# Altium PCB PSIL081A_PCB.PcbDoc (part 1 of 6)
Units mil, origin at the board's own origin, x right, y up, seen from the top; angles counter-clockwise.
Board outline 14000 x 8000 mil, 10 copper layers (Top Layer, Signal Layer 1, Signal Layer 2, Signal Layer 3, Signal Layer 4, Signal Layer 5, Signal Layer 6, Signal Layer 7, Signal Layer 8, Bottom Layer), stack 60.9 mil thick; 433 components, 510 nets, 1716 pads, 590 vias.
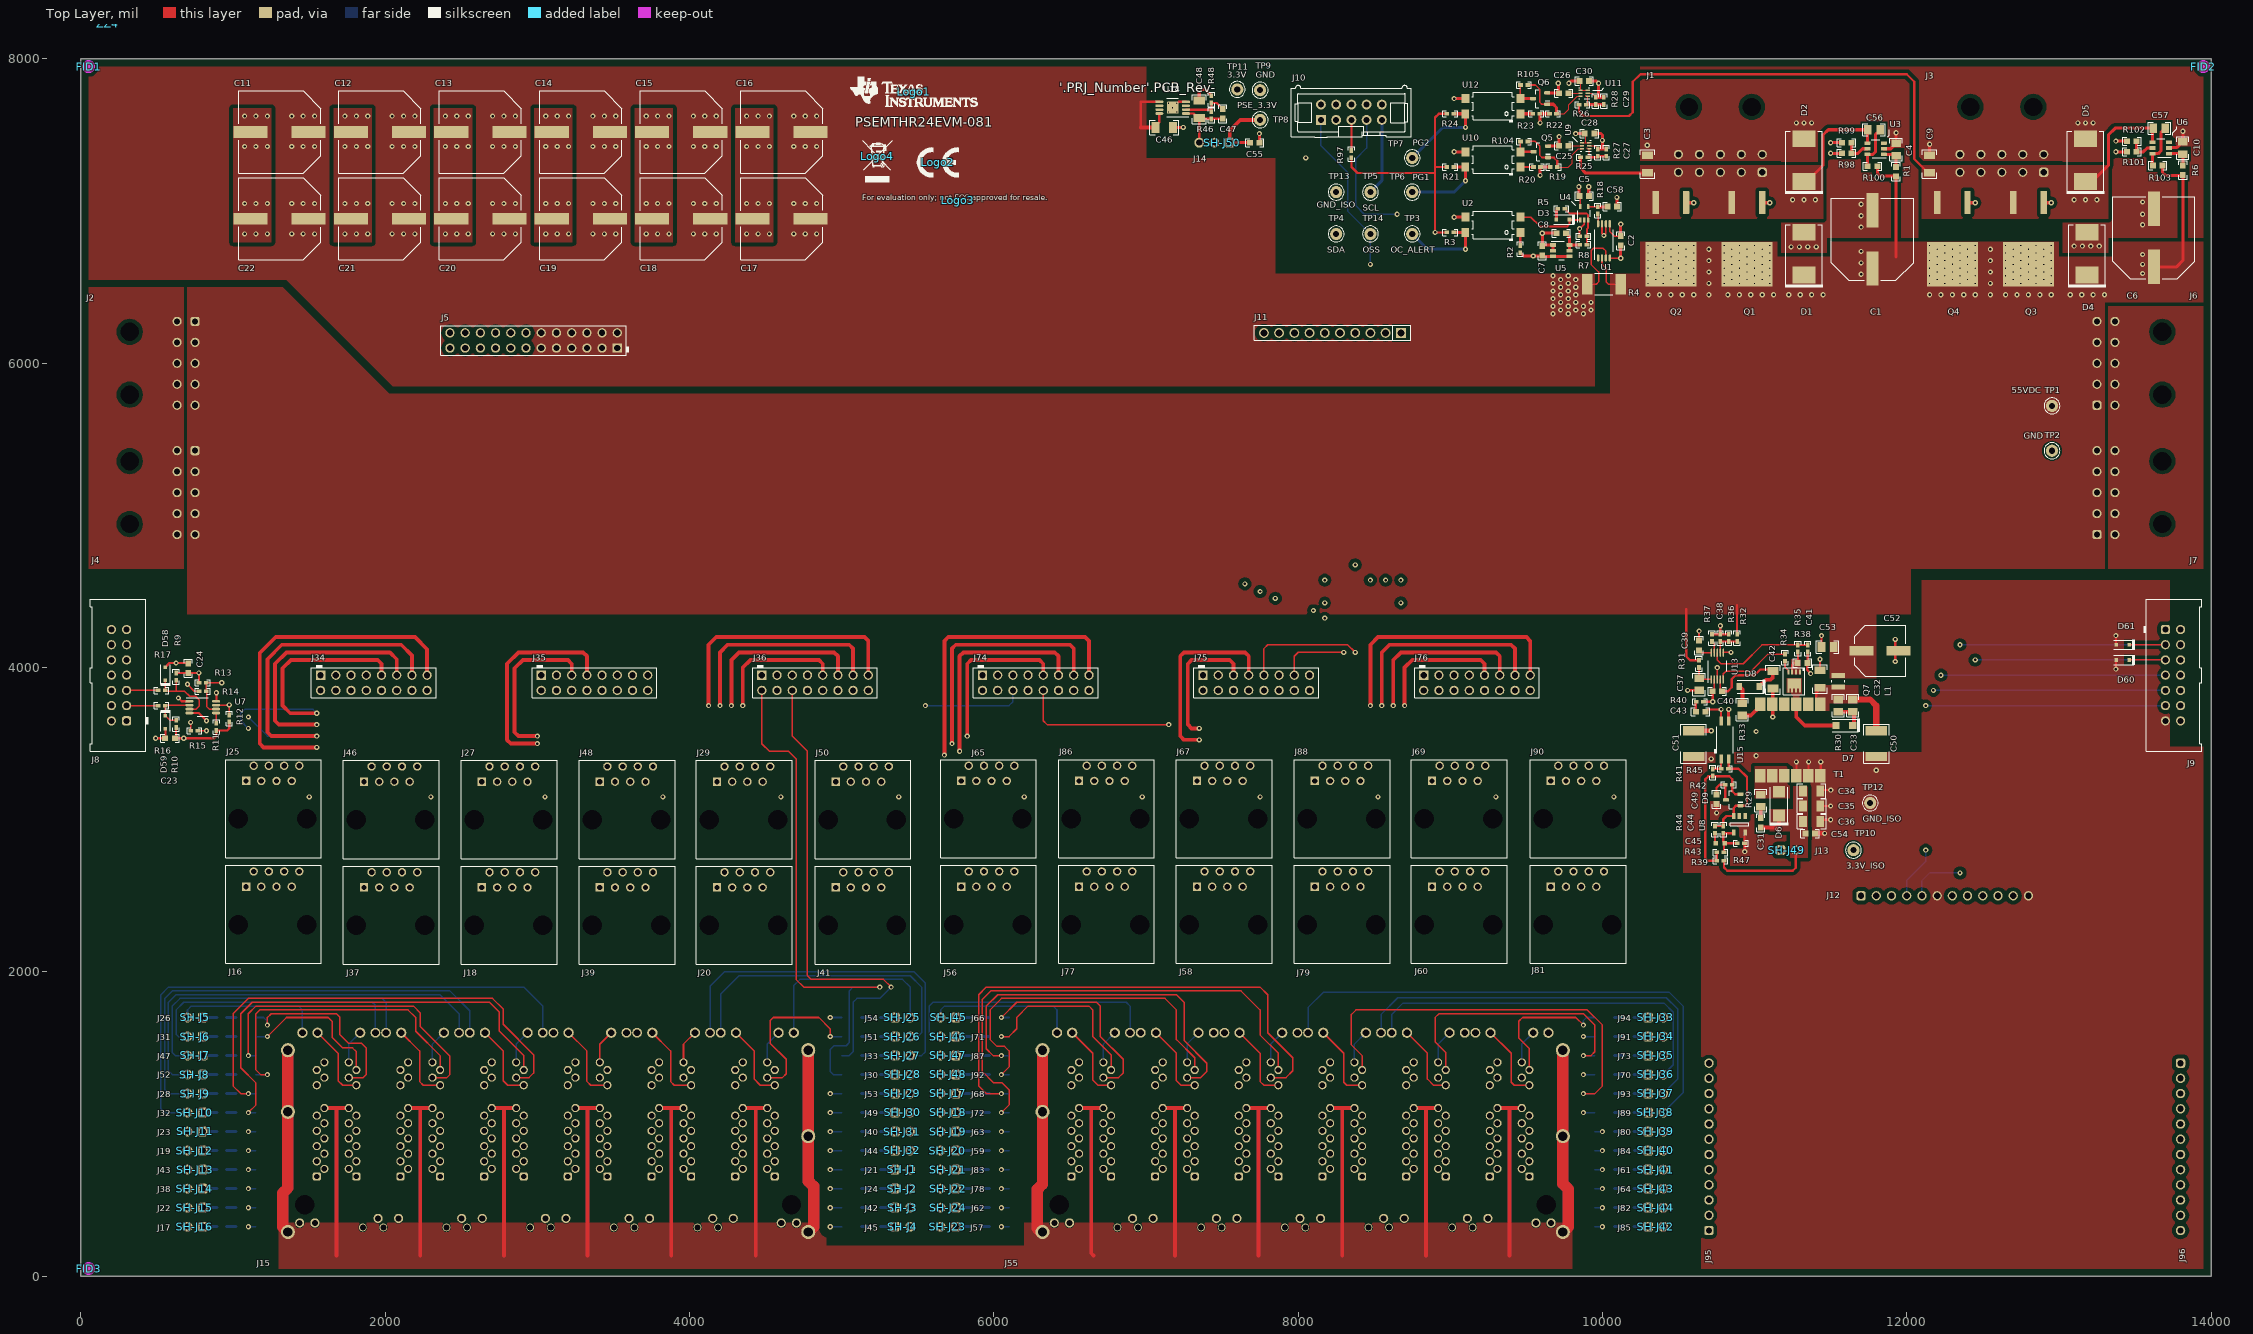
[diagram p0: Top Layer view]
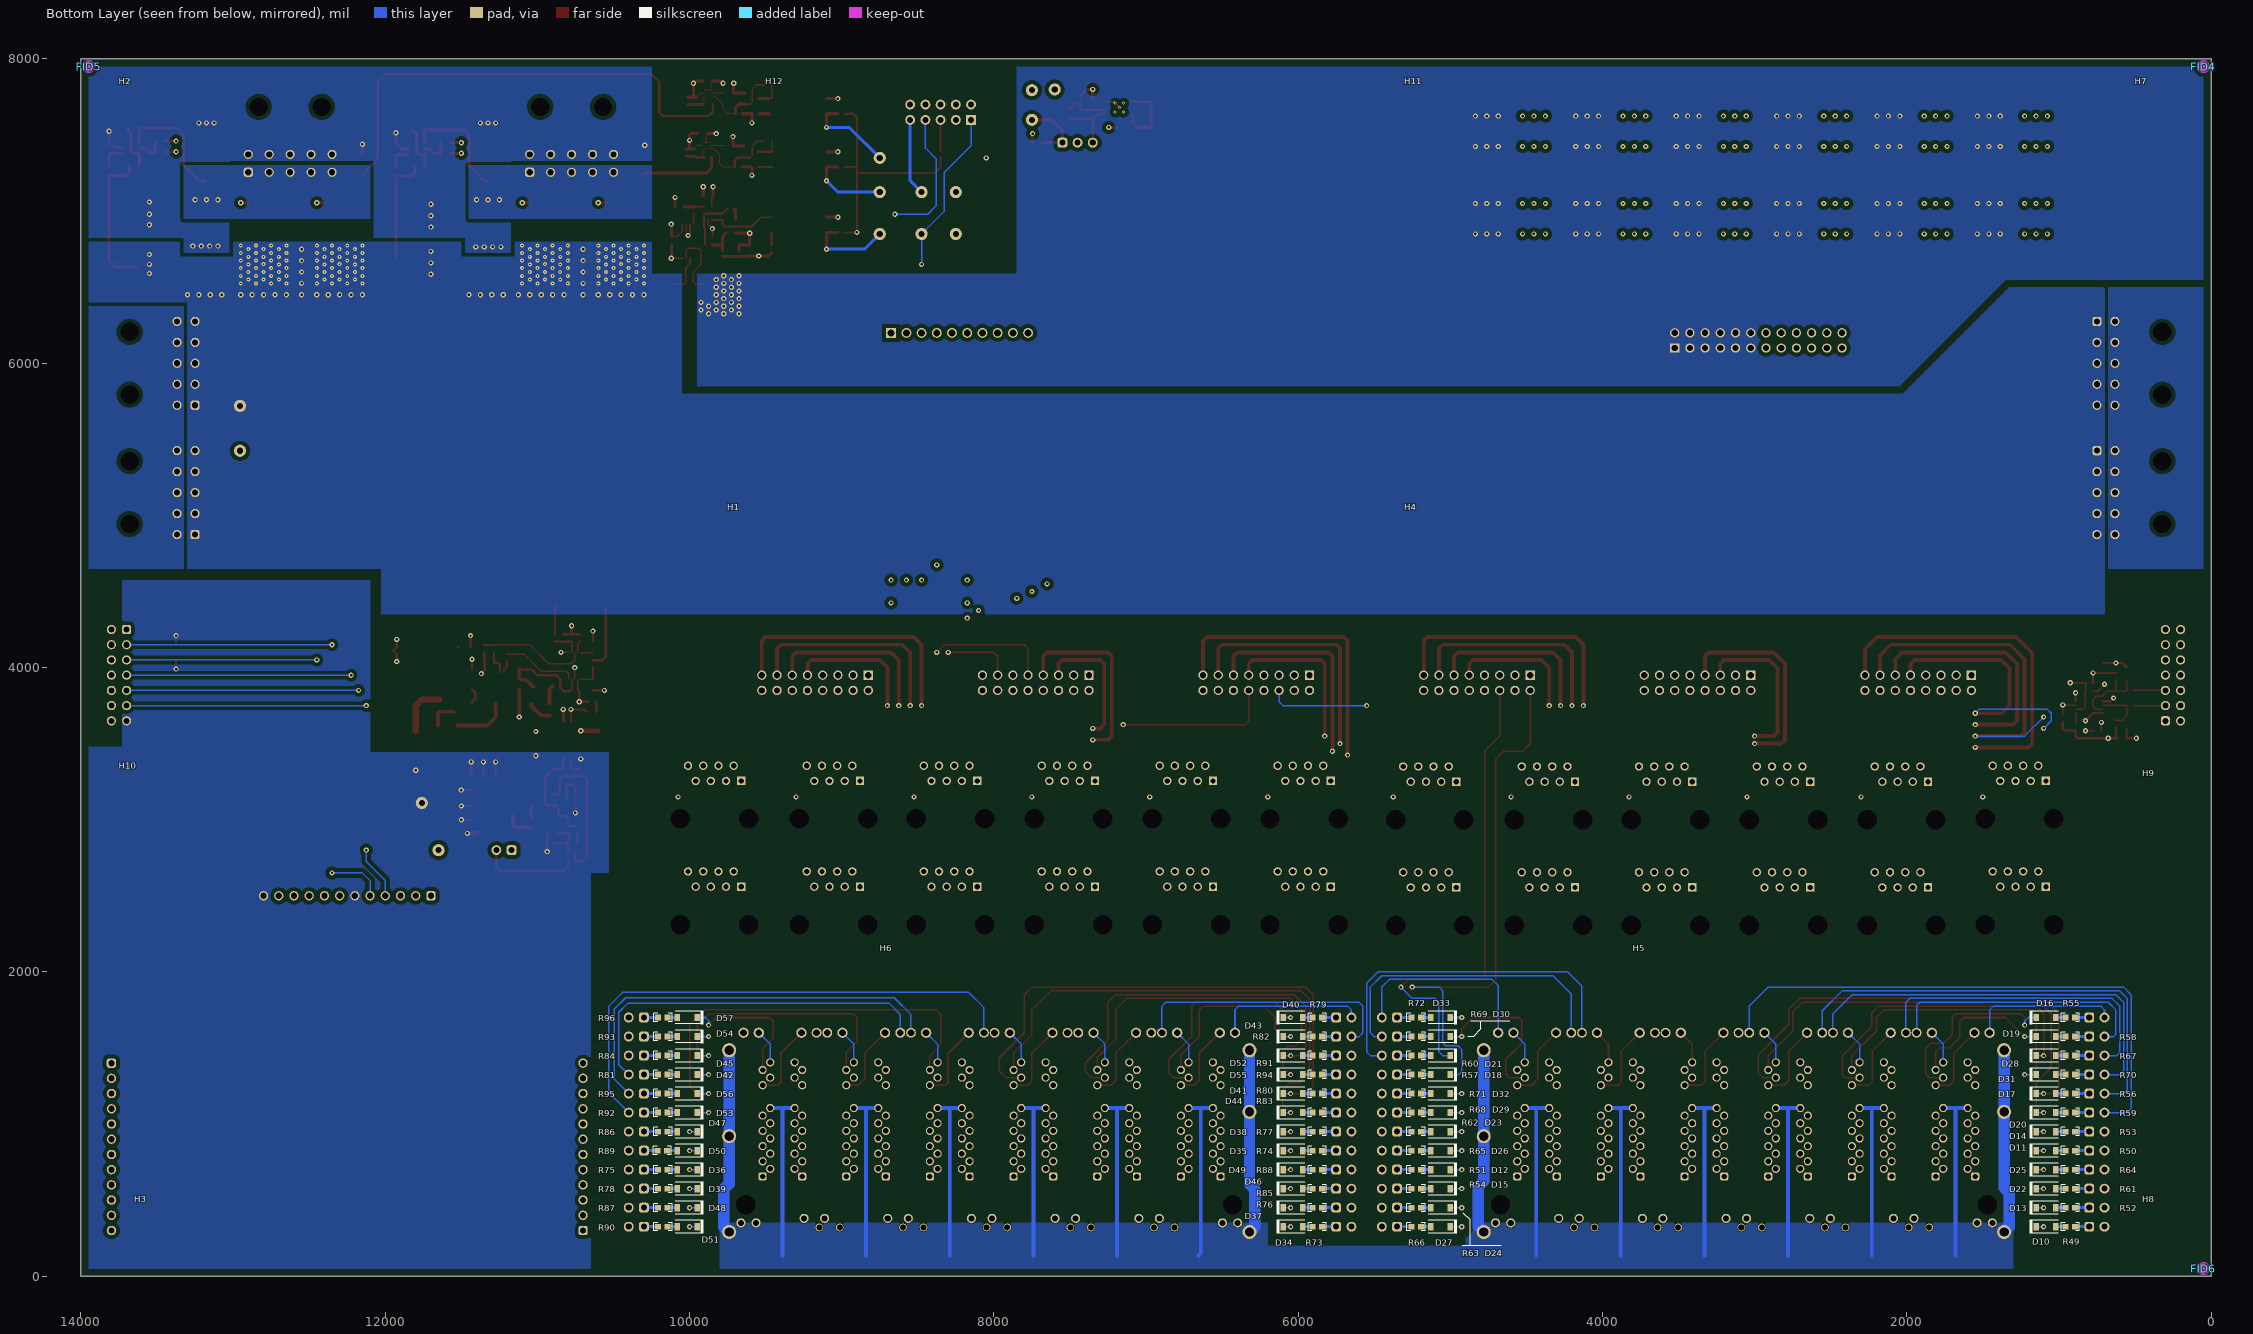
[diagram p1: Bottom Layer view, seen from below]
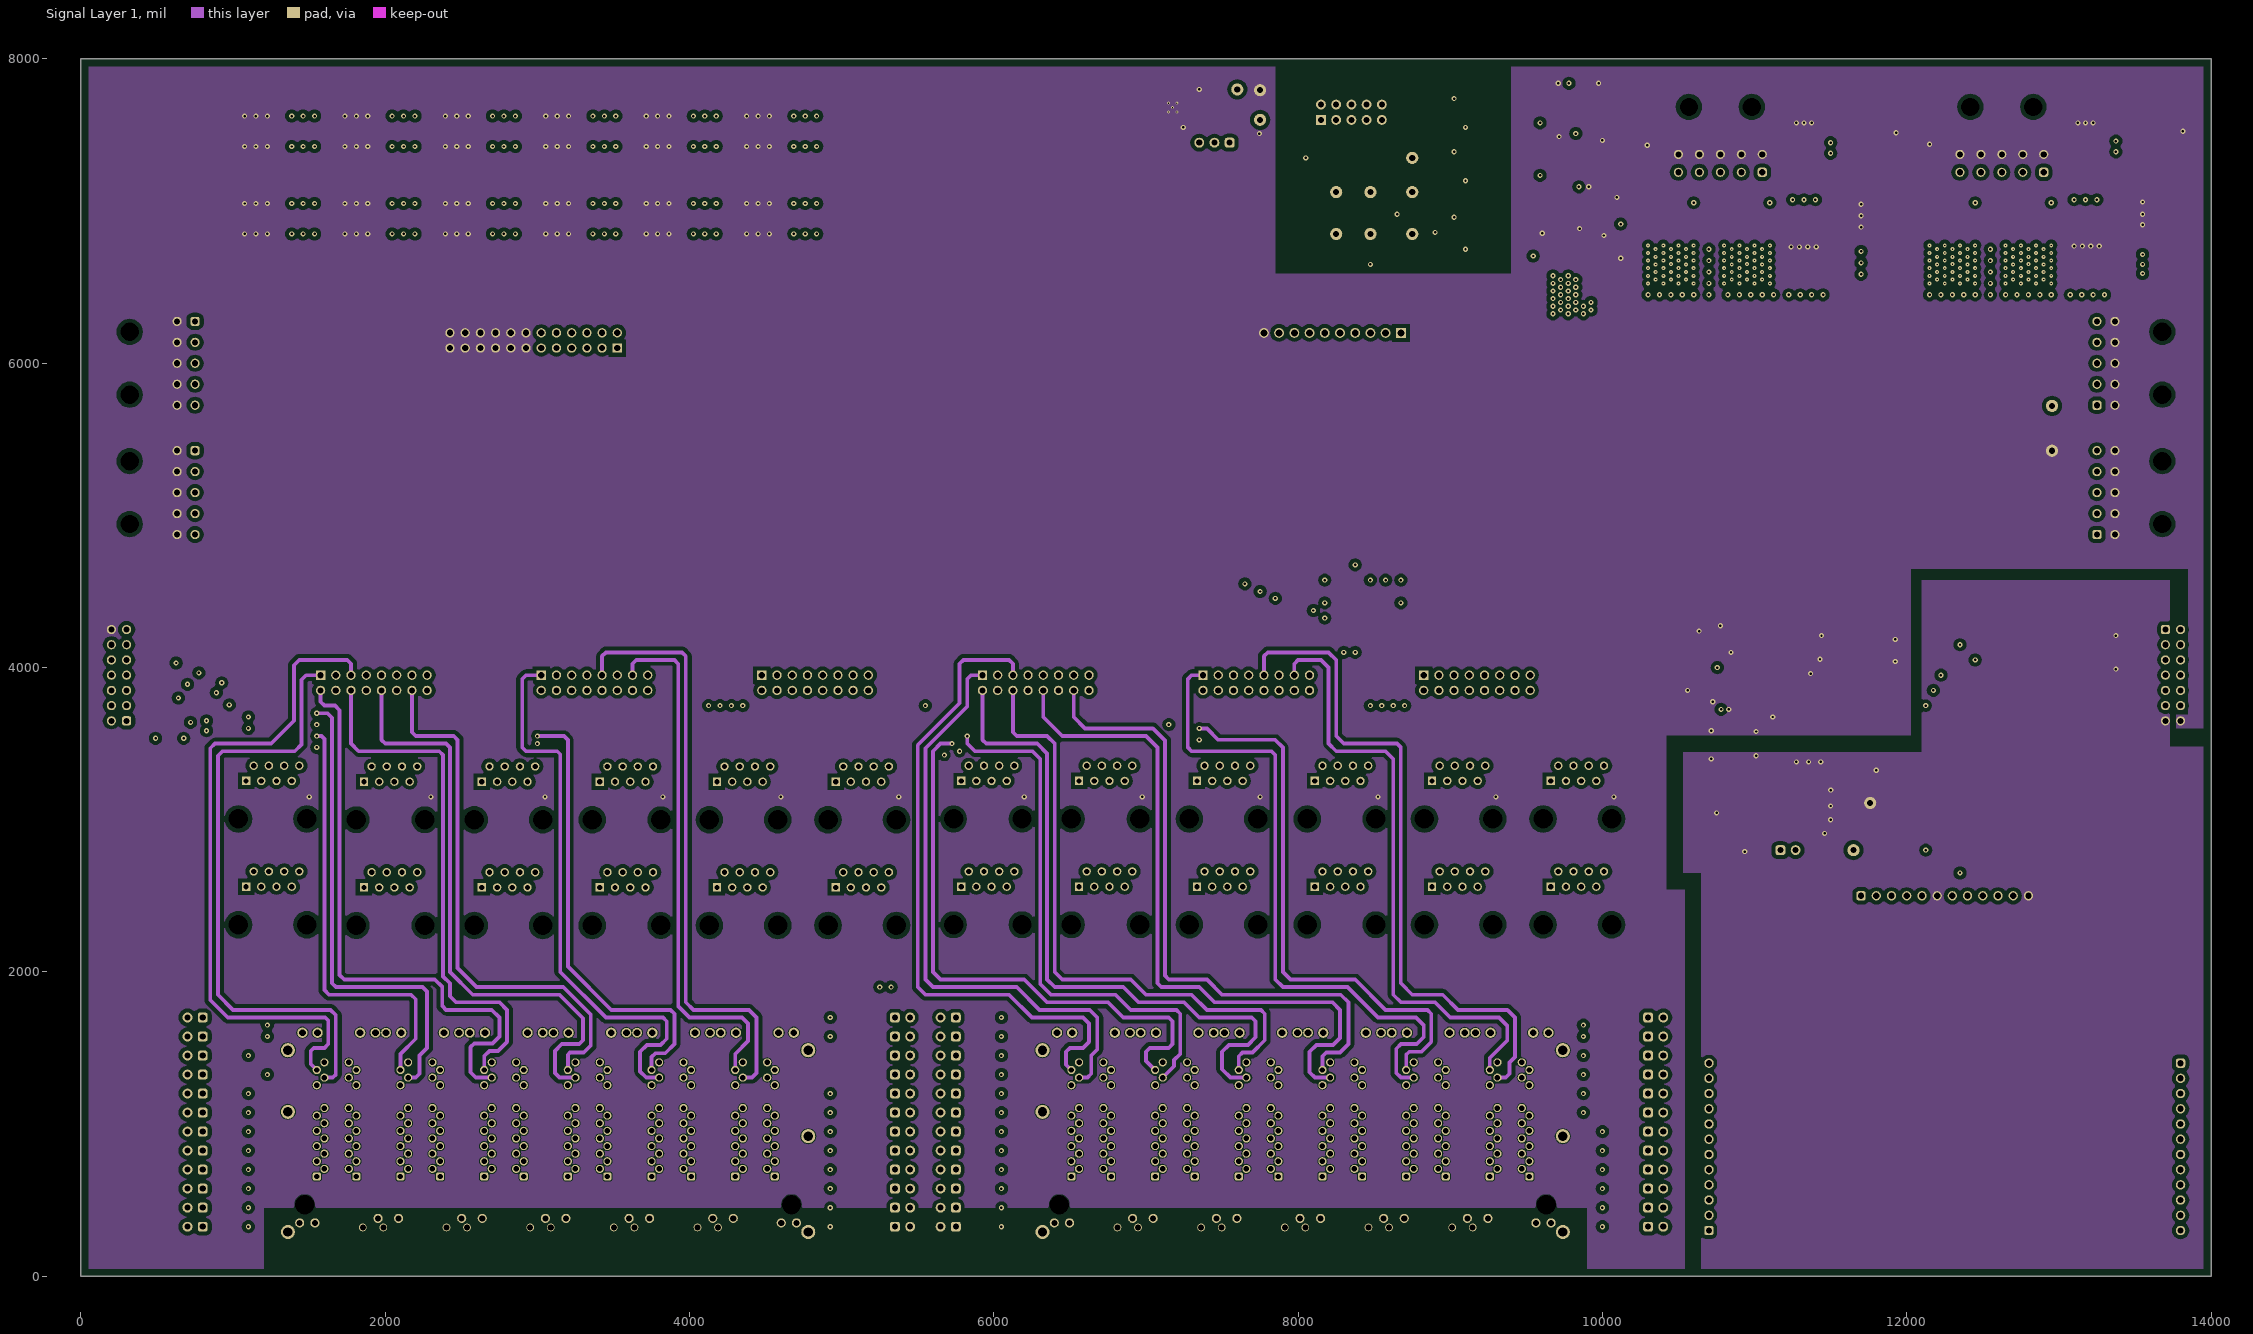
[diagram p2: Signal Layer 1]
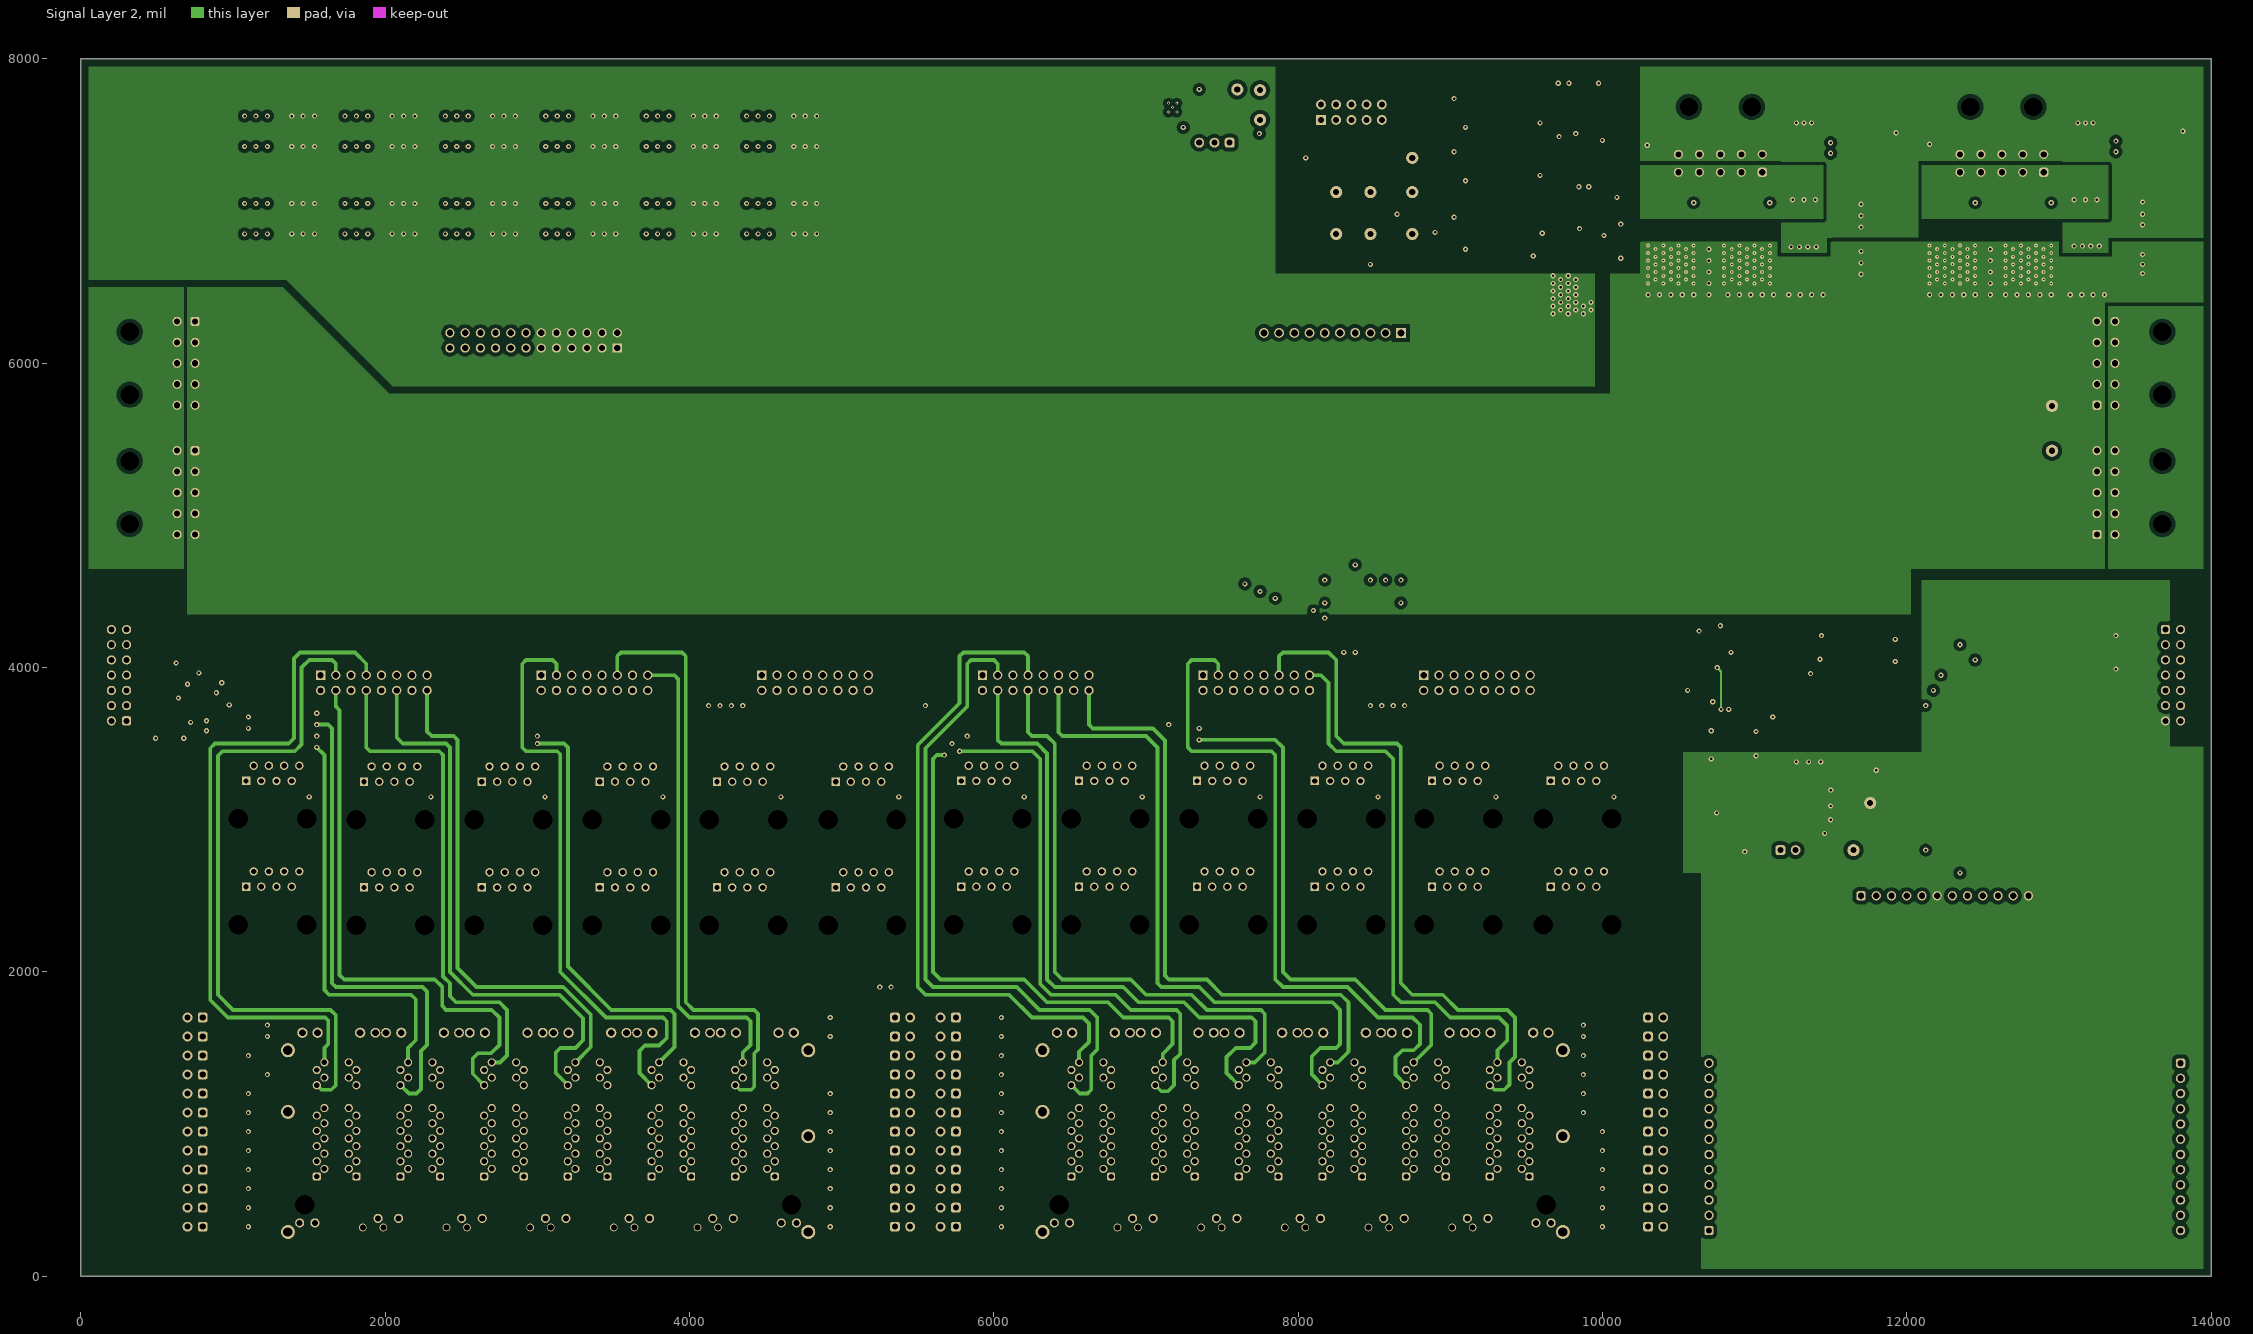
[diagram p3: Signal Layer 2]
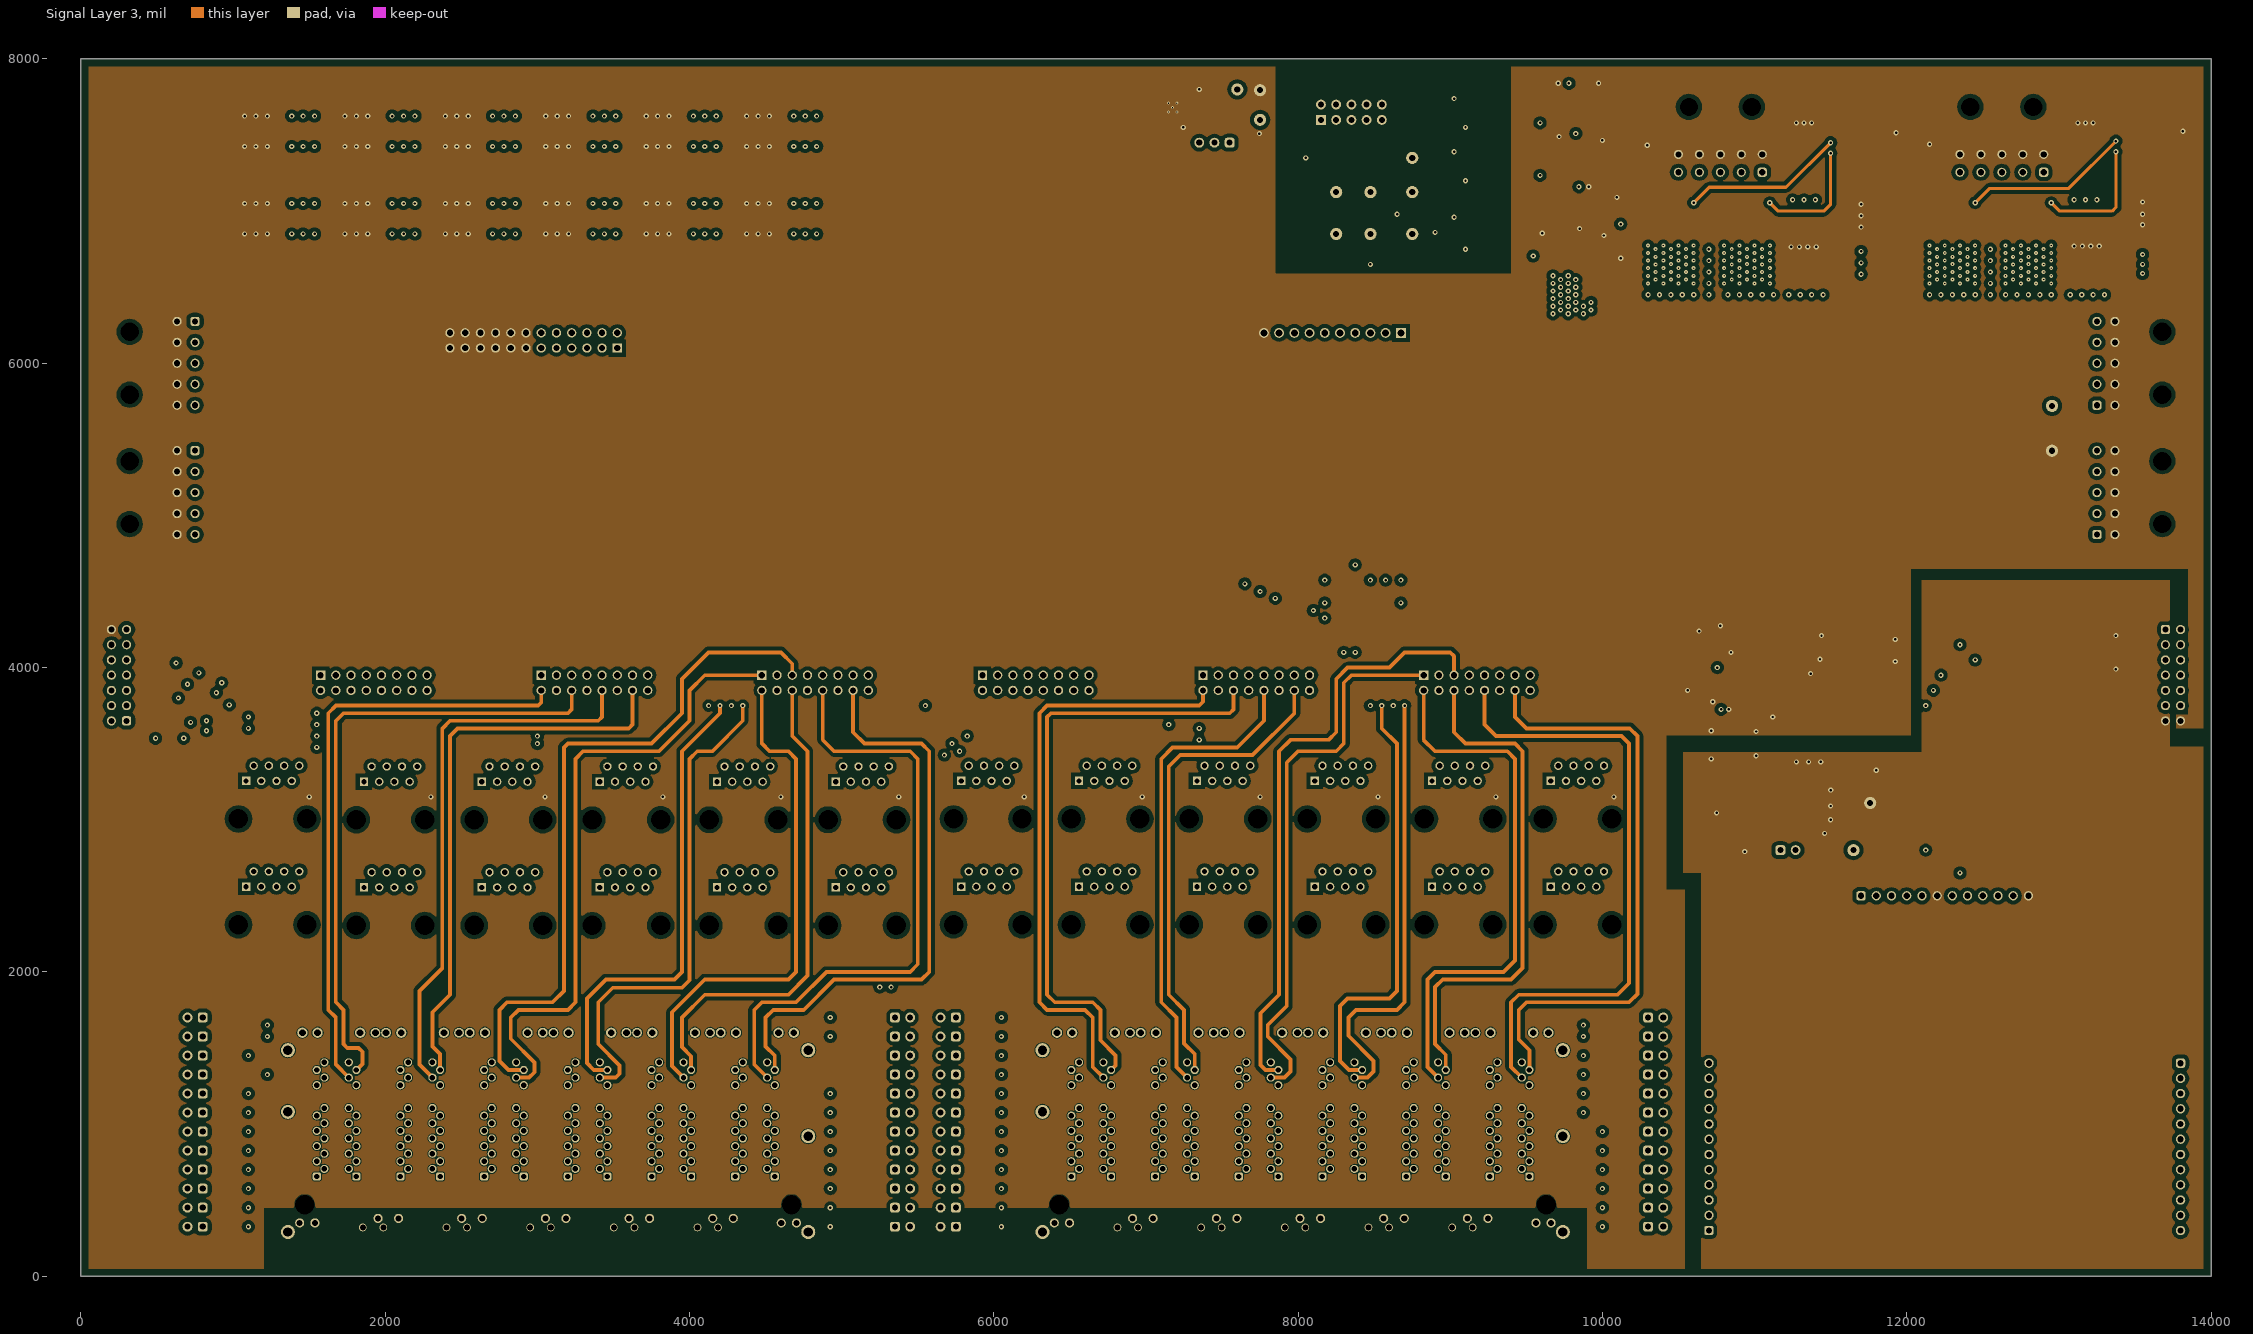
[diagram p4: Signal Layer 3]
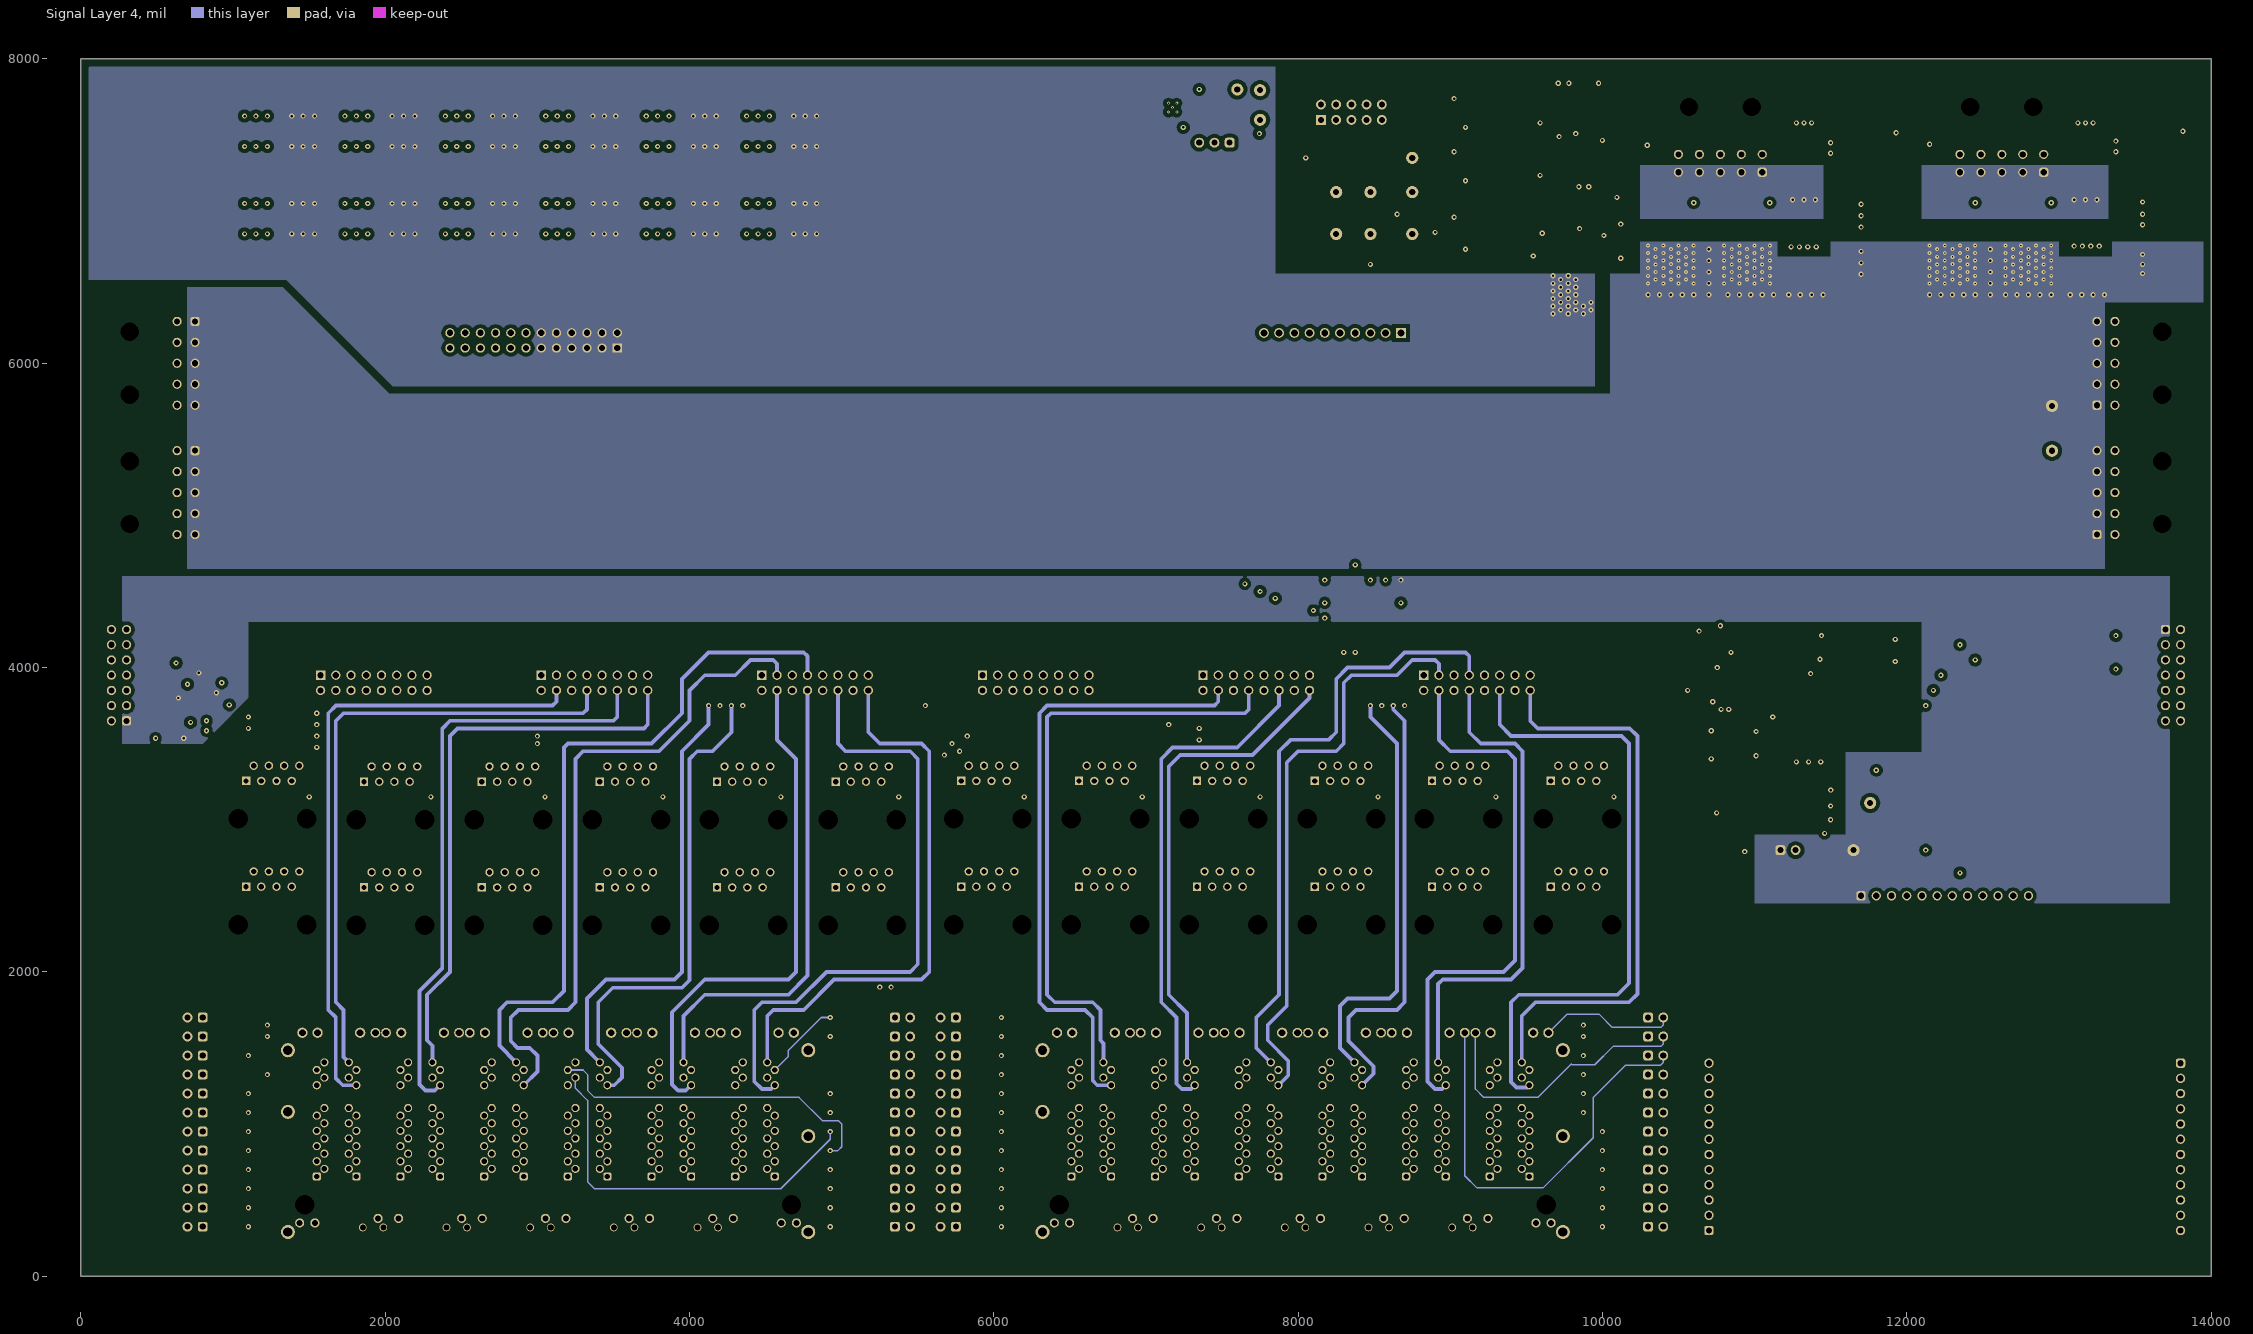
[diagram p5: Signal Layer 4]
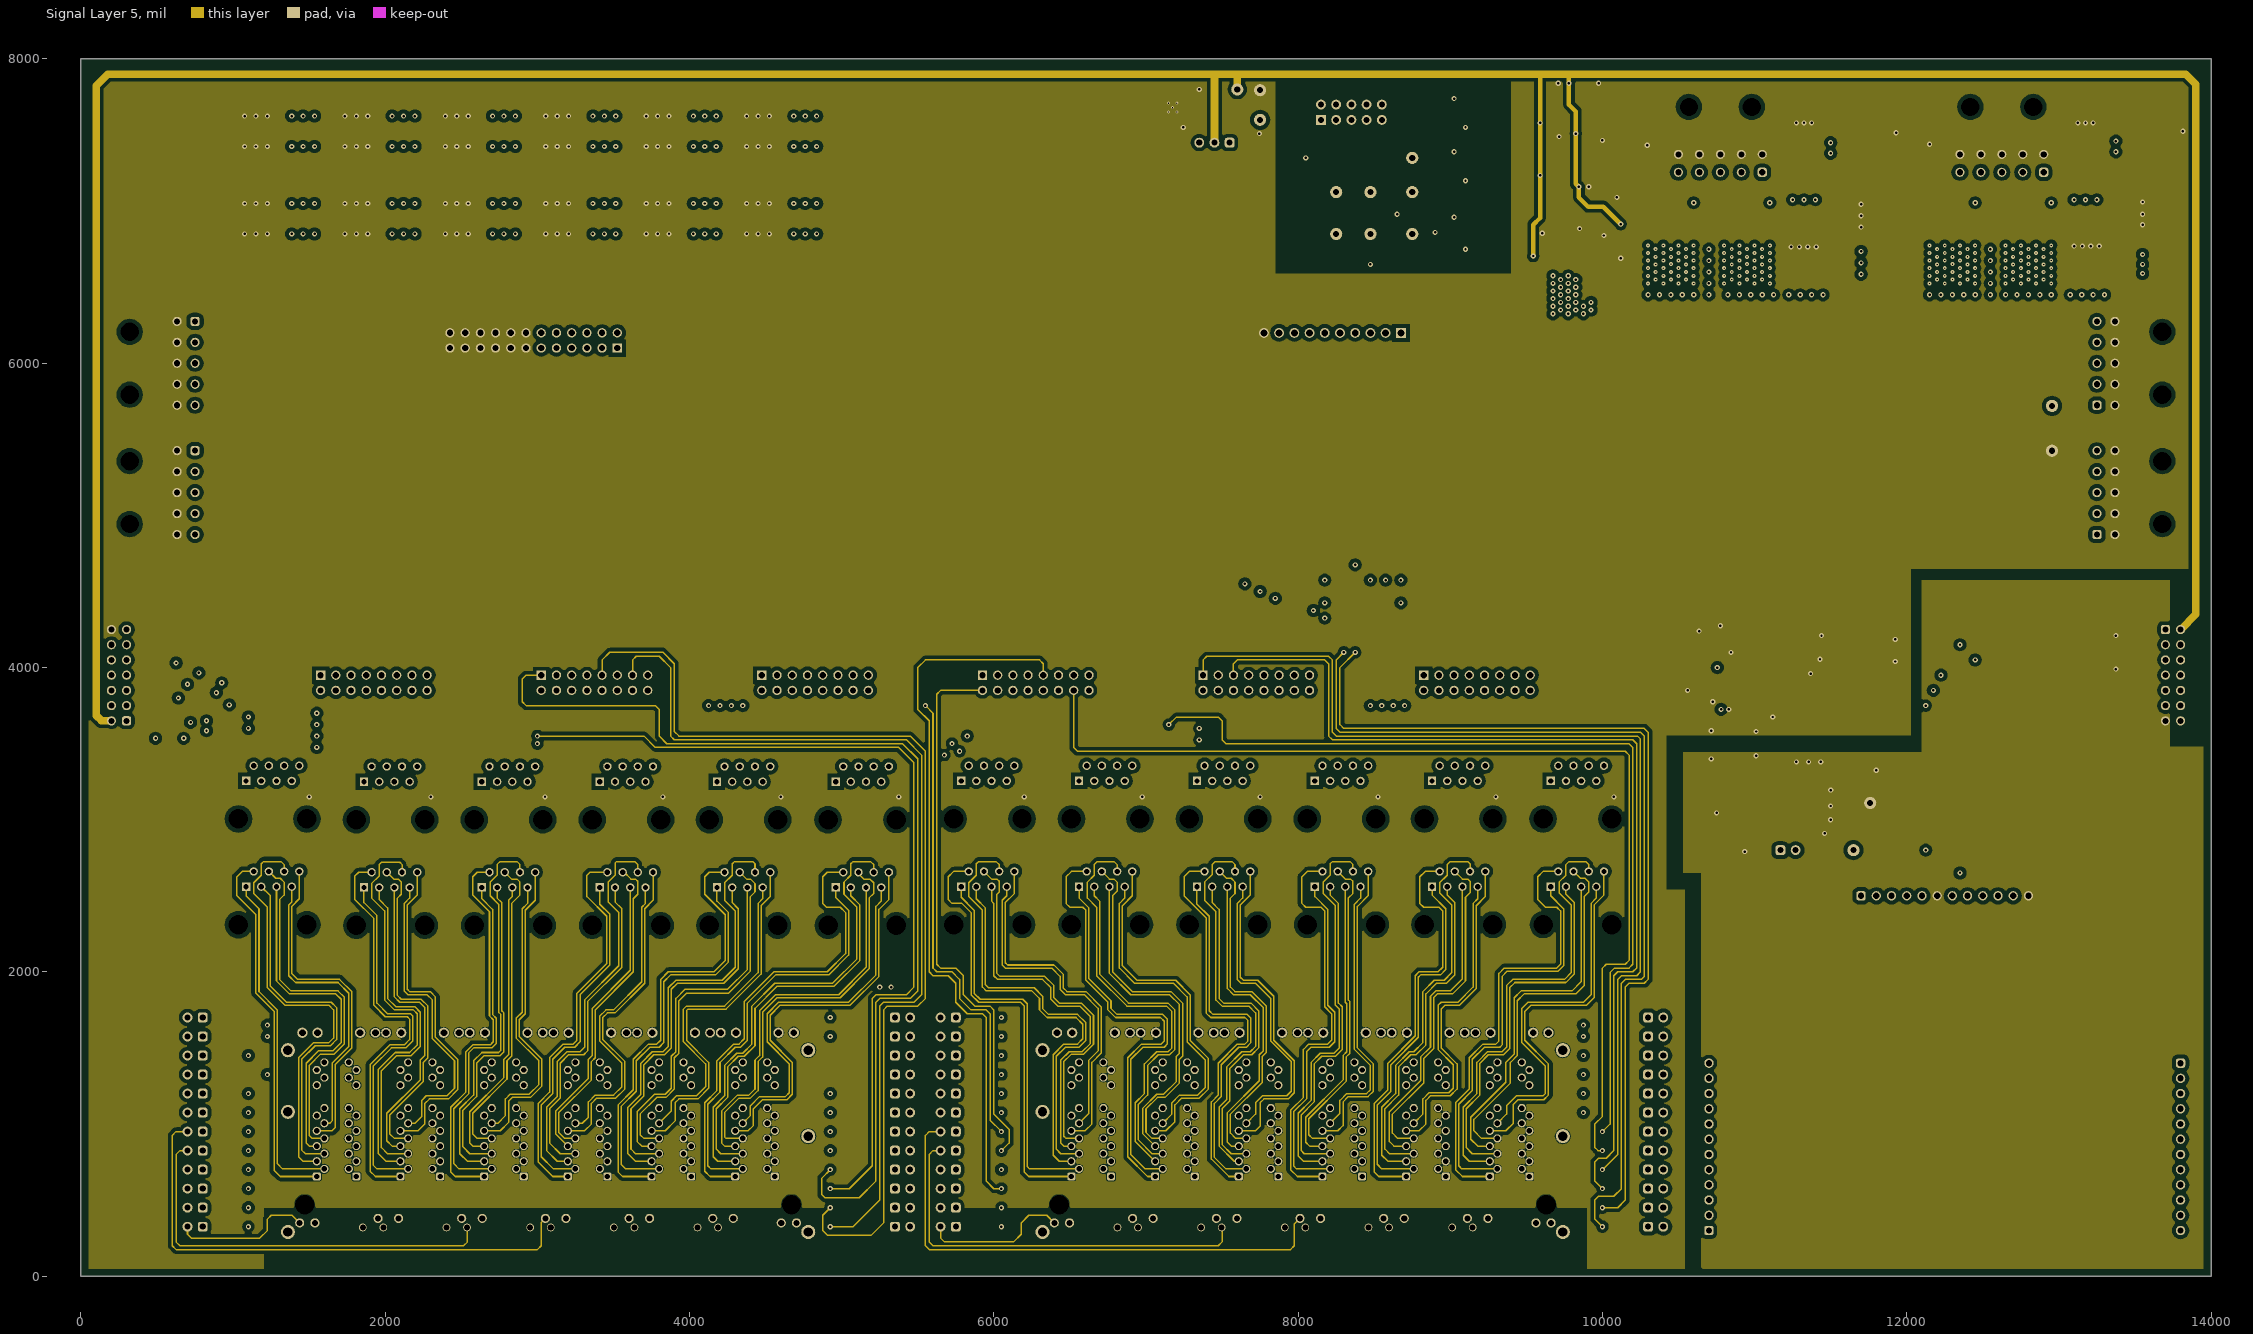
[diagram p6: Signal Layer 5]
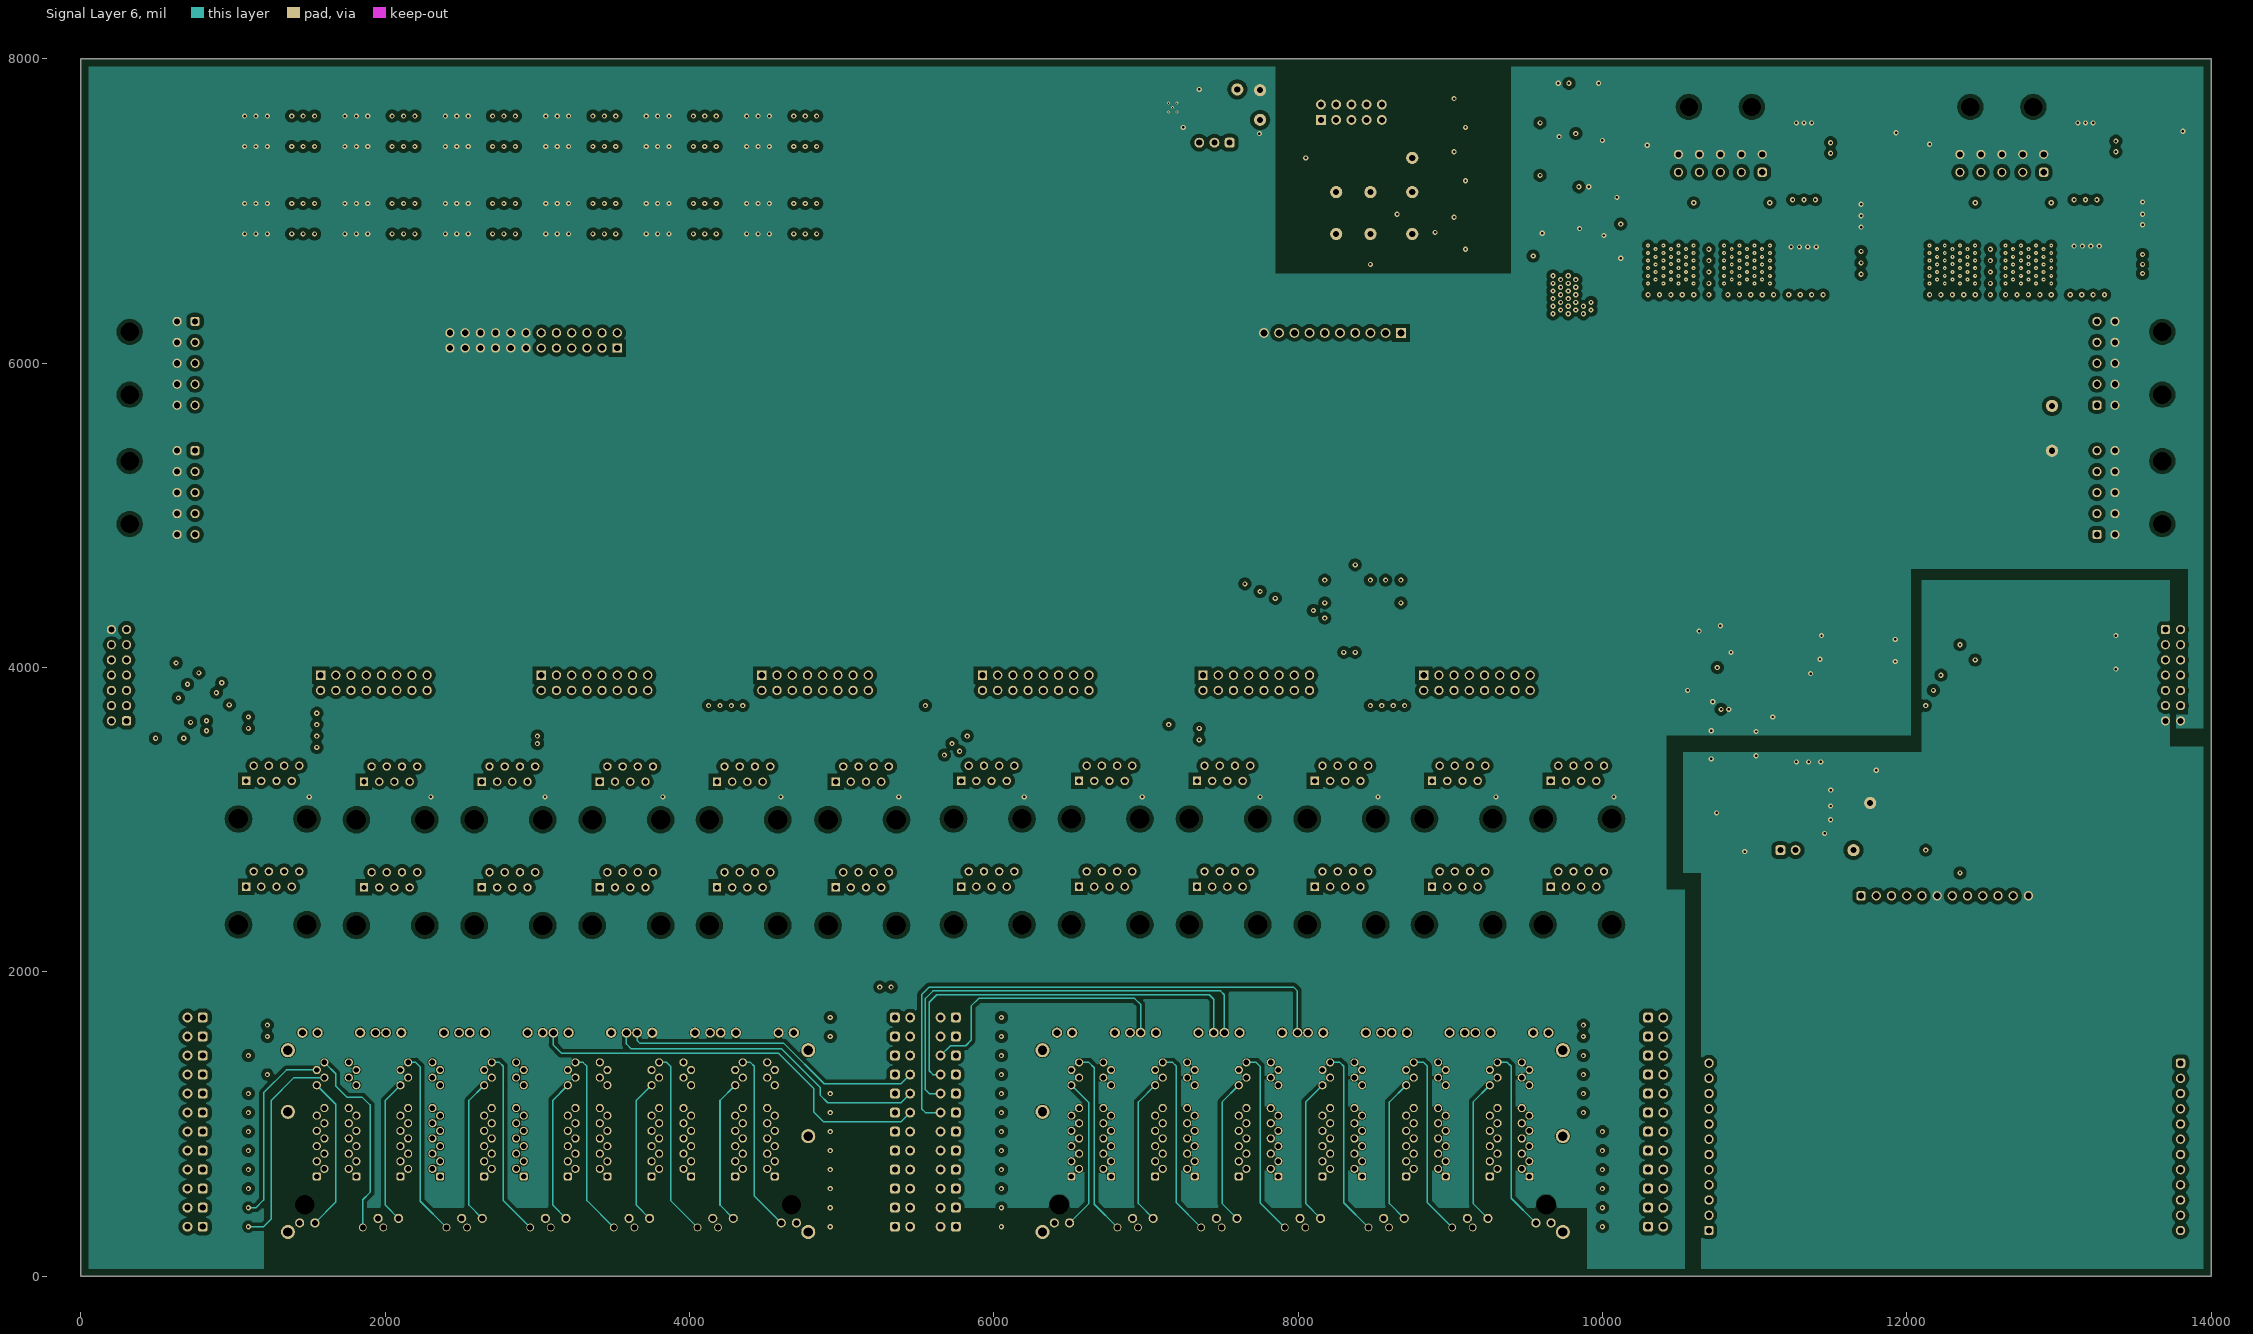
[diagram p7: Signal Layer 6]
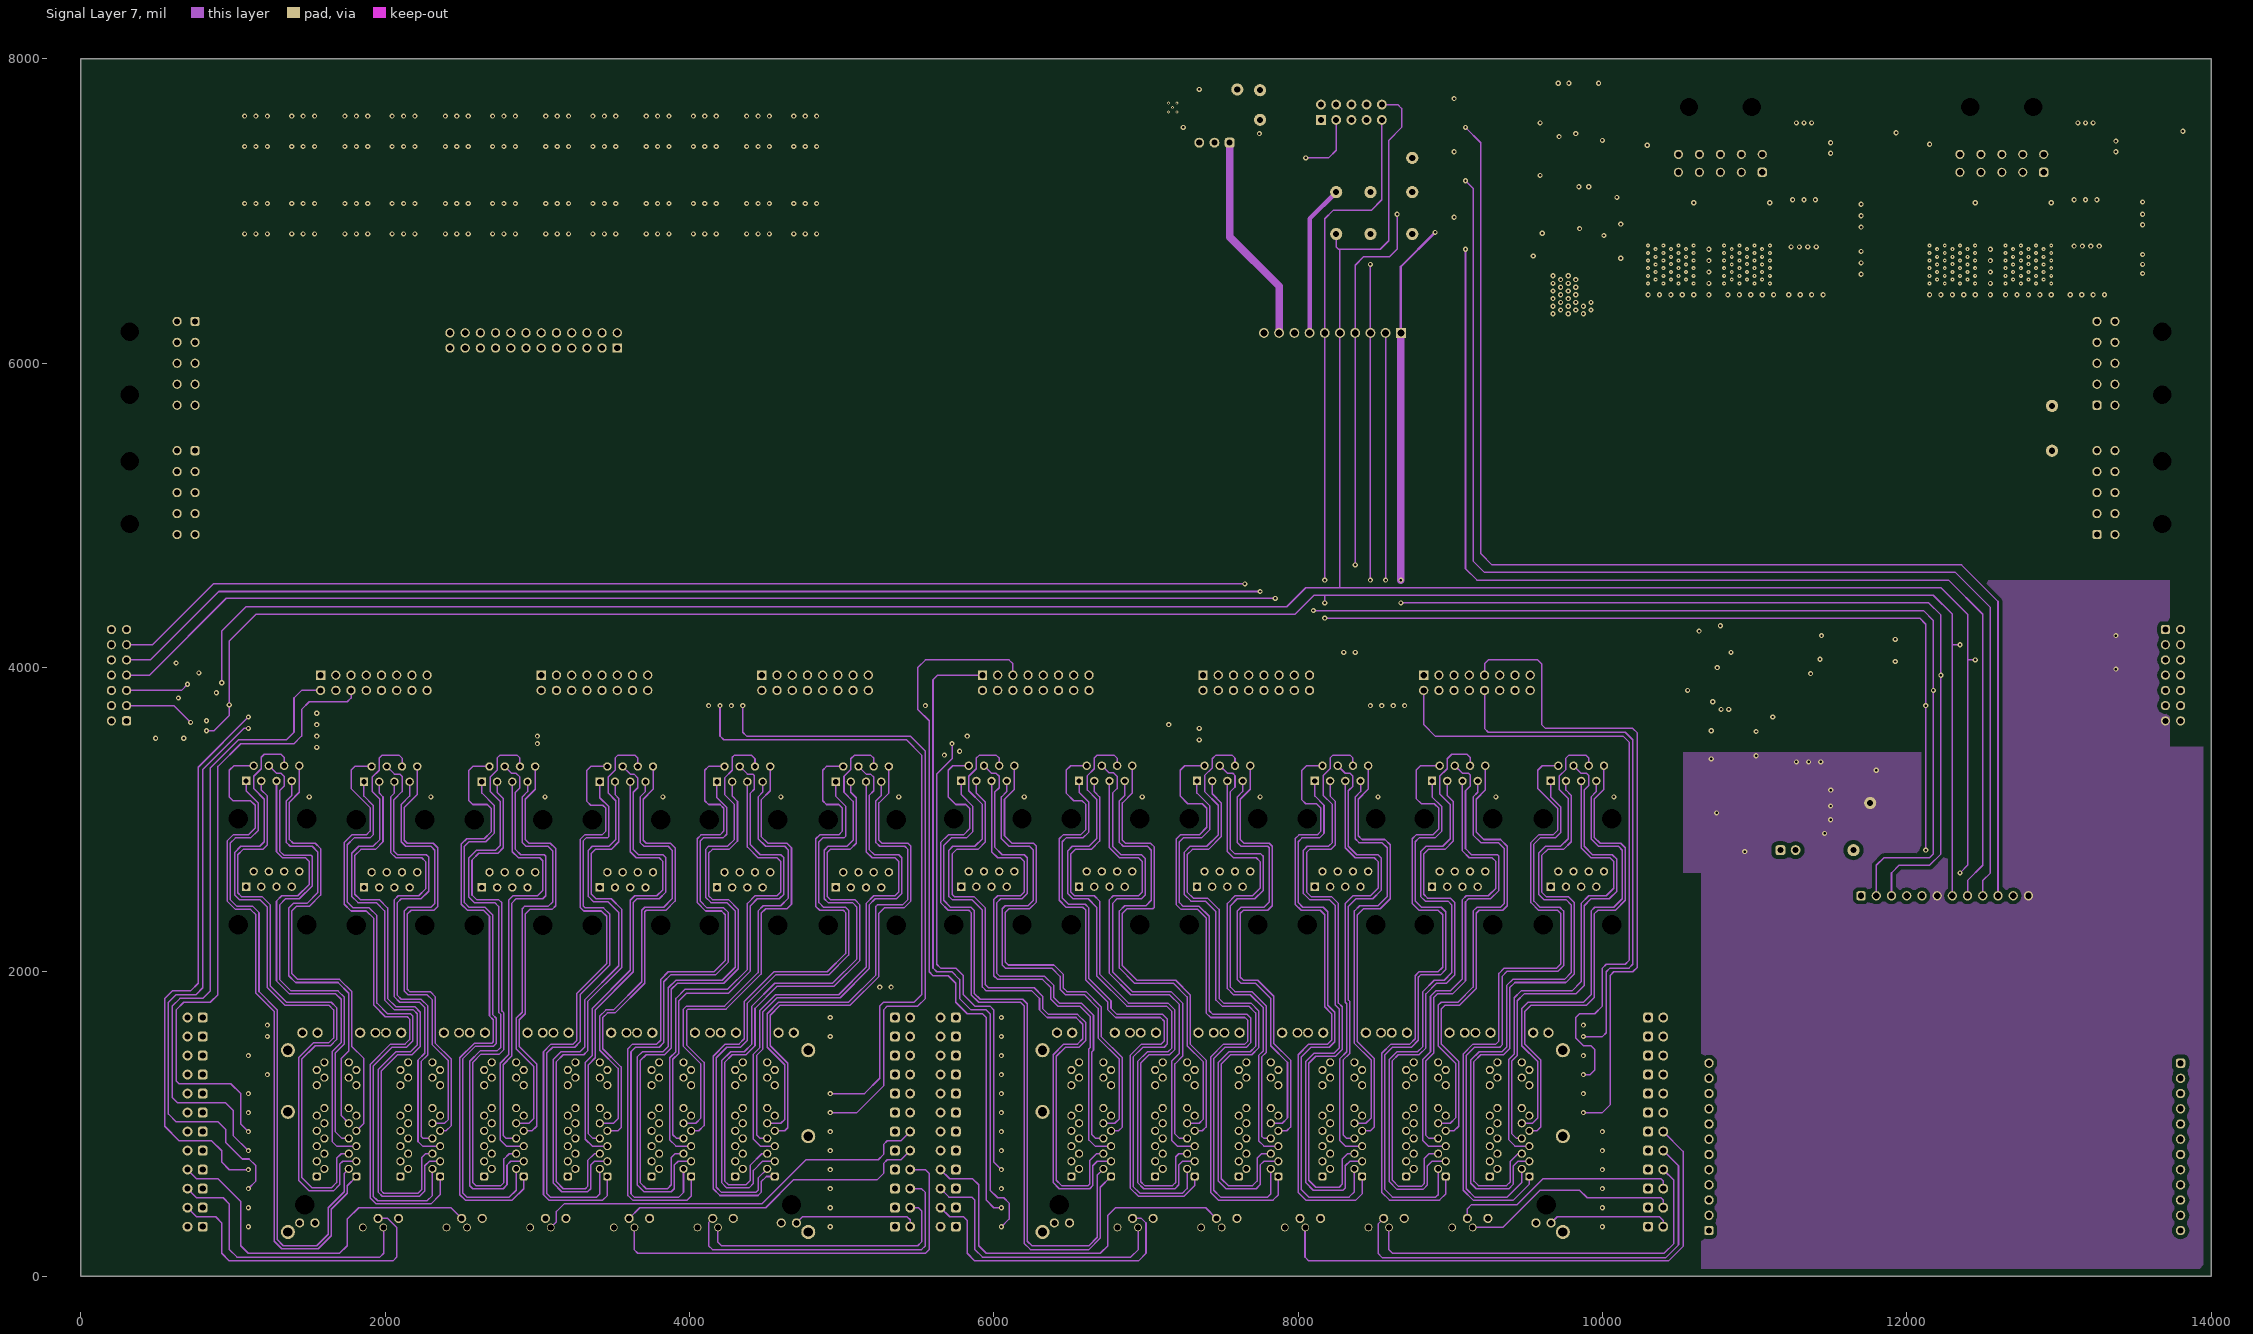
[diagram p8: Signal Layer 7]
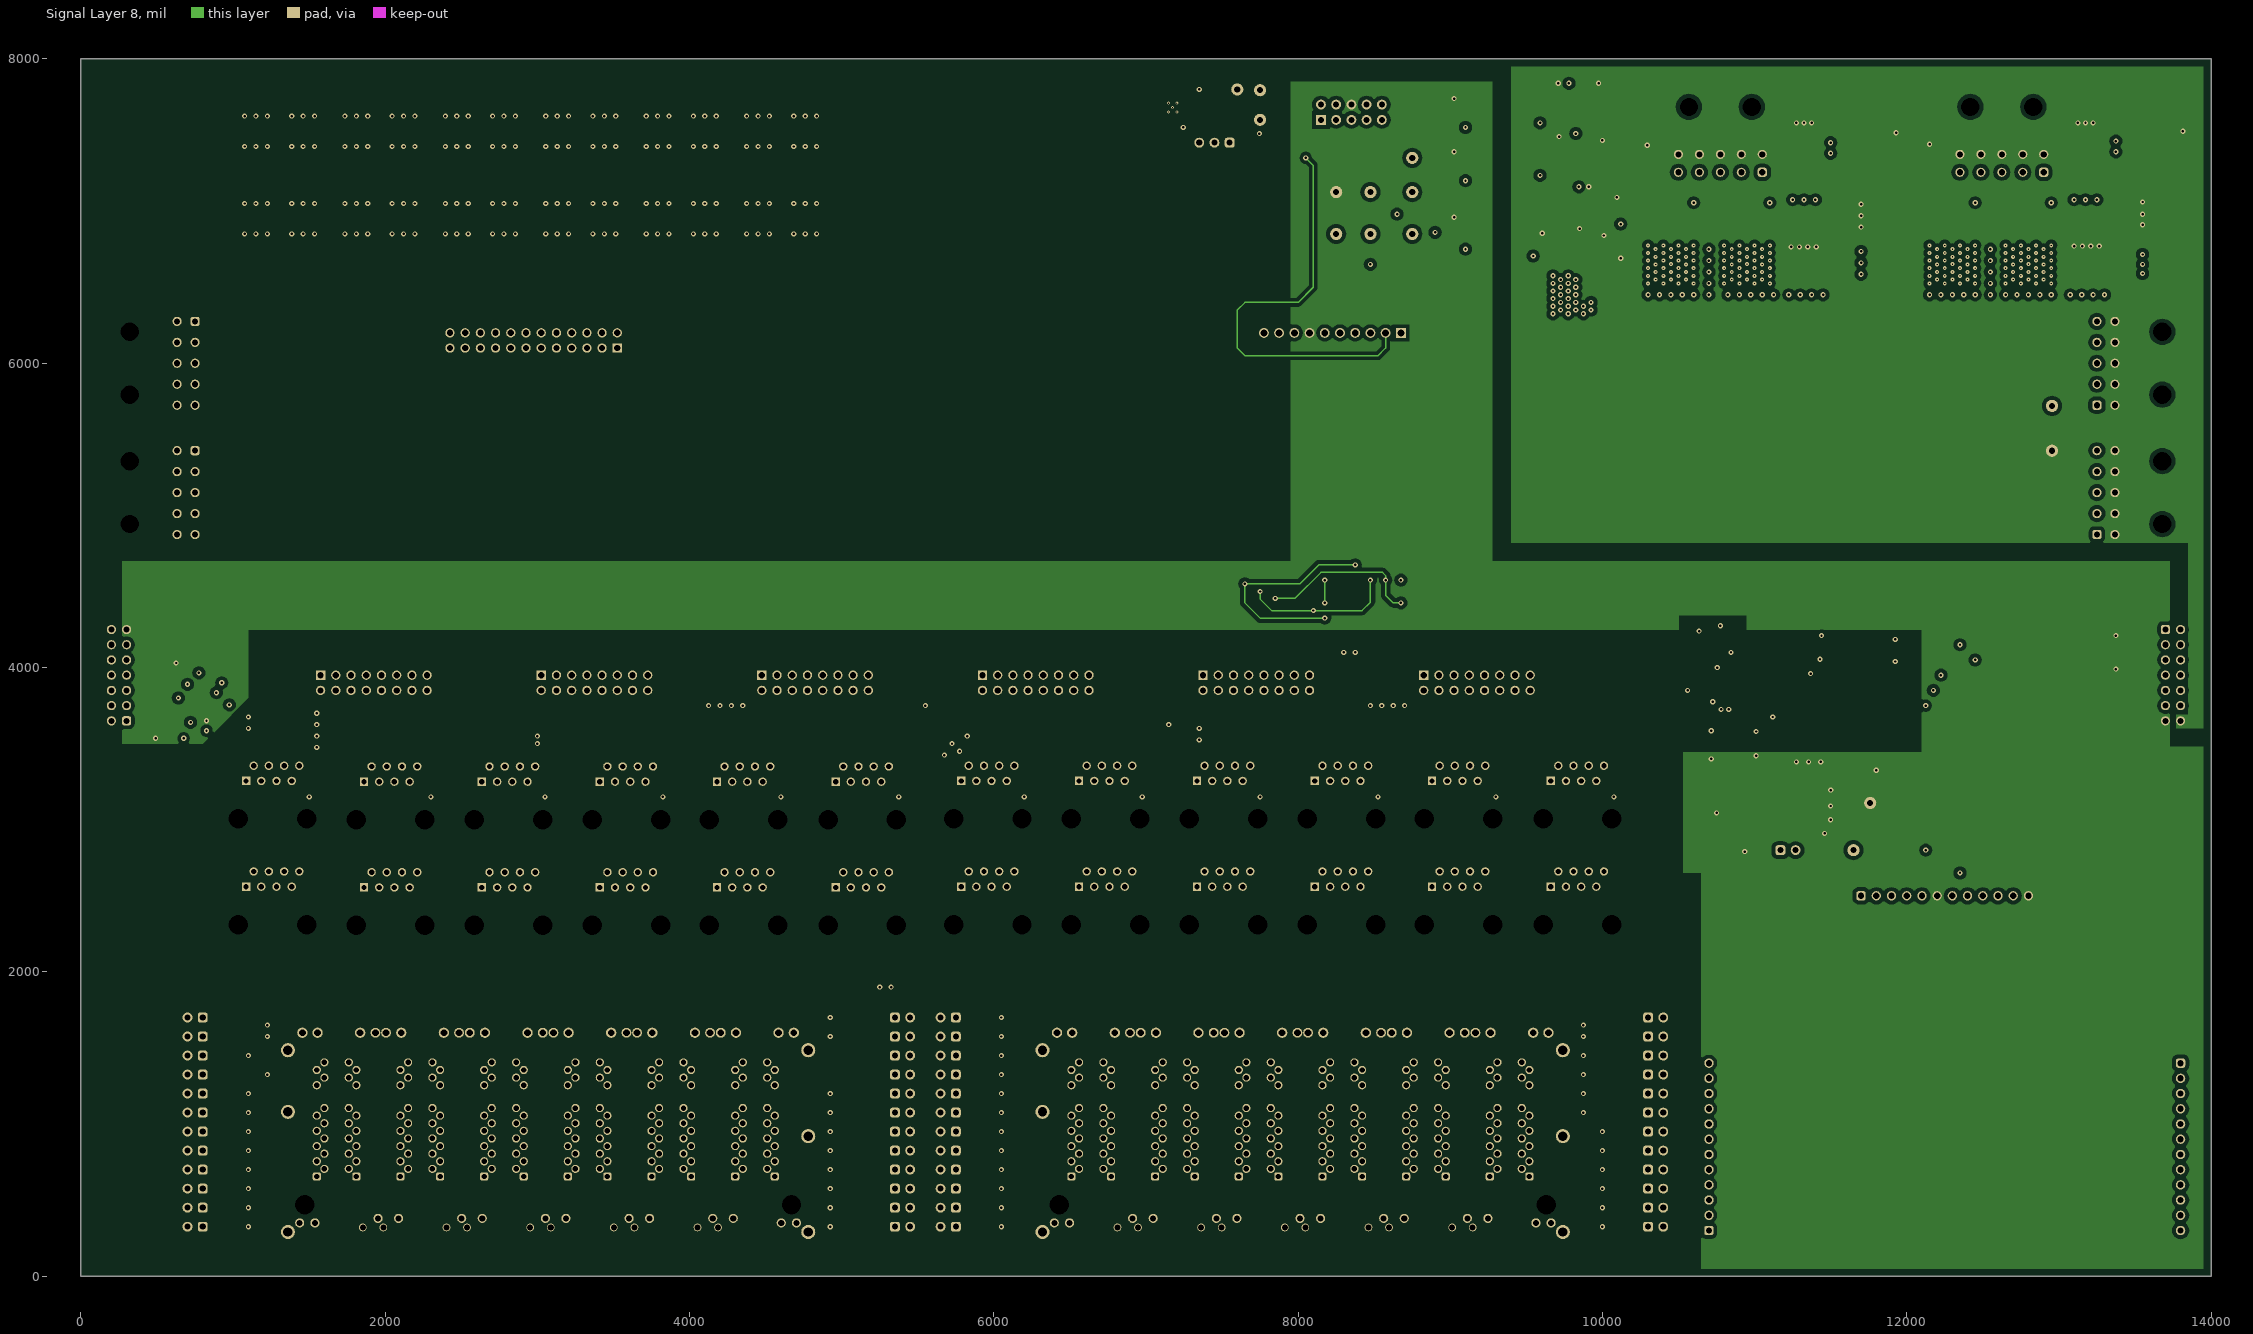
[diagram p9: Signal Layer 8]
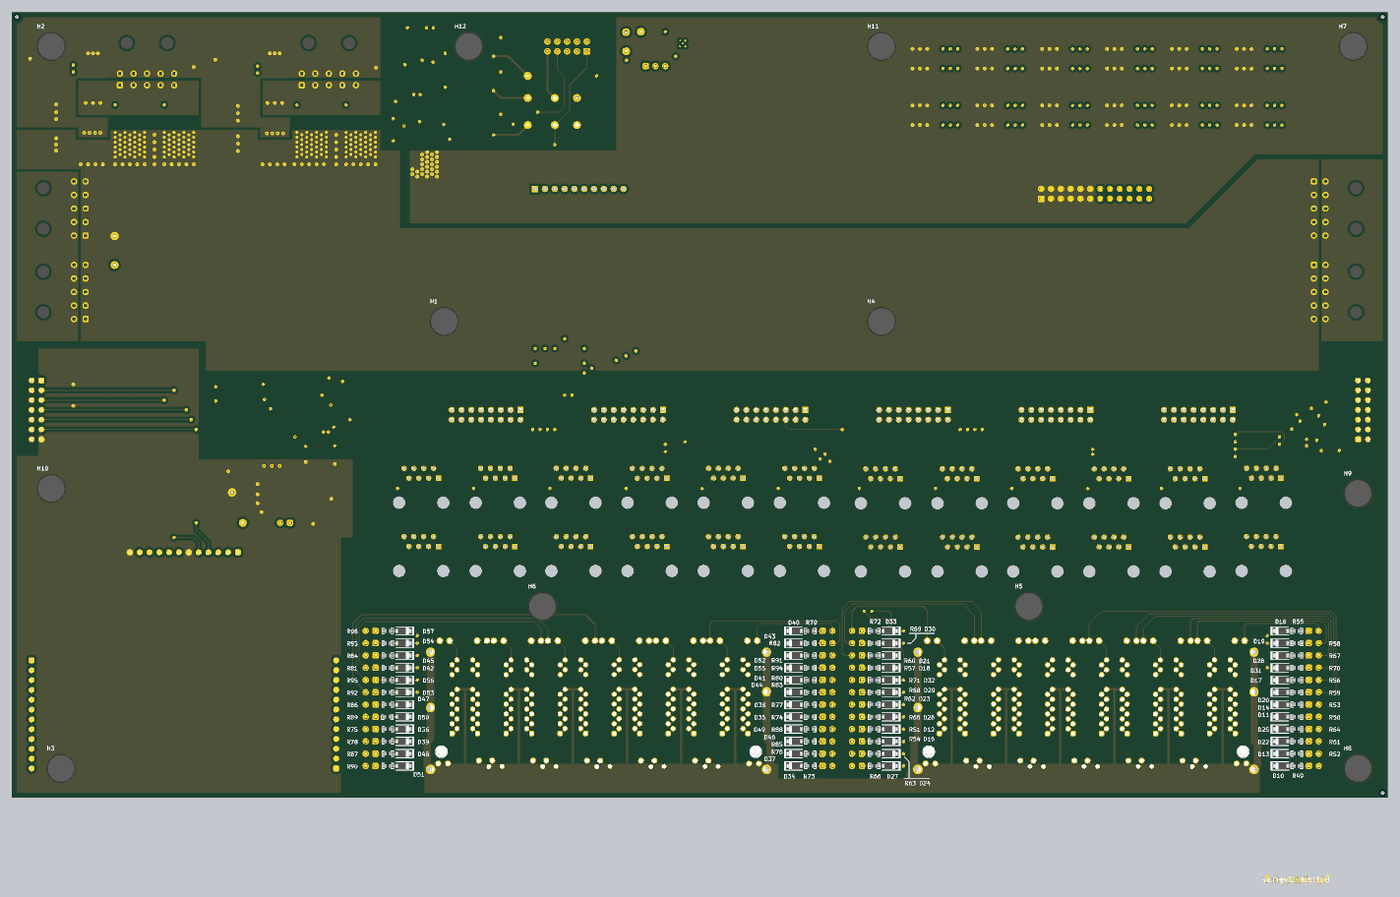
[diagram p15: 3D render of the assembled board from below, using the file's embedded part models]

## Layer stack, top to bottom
Top Solder: solder mask 0.4, Solder Resist, Dk 3.5
Top Layer: signal copper 1.9
Dielectric1: prepreg 5.8, FR-4, Dk 4.2
Signal Layer 1: signal copper 1.2
Dielectric 2: core 5, FR-4, Dk 4.2
Signal Layer 2: signal copper 1.2
Dielectric 3: prepreg 5.2, FR-4, Dk 4.2
Signal Layer 3: signal copper 1.2
Dielectric 4: core 5, FR-4, Dk 4.2
Signal Layer 4: signal copper 1.2
Dielectric 5: prepreg 5.5, FR-4, Dk 4.2
Signal Layer 5: signal copper 1.2
Dielectric 6: core 5, FR-4, Dk 4.2
Signal Layer 6: signal copper 1.2
Dielectric 7: prepreg 5.2, FR-4, Dk 4.2
Signal Layer 7: signal copper 1.2
Dielectric 8: core 5, FR-4, Dk 4.2
Signal Layer 8: signal copper 1.2
Dielectric 9: prepreg 5.8, FR-4, Dk 4.2
Bottom Layer: signal copper 1.9
Bottom Solder: solder mask 0.4, Solder Resist, Dk 3.5

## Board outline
0,0 14000,0 14000,8000 0,8000

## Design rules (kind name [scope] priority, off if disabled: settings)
AcuteAngle [All] p1: minimum=4.50000000000000E+0001 checktracksonly=FALSE
AssemblyTestPointUsage [All] p1: valid=2
BoardOutlineClearance BoardOutlineClearance_MountingHoles [OnCopper and InComponentClass('Mounting Holes')] p1: gap=40 ignorepadtopadclearanceinfootprint=FALSE
BoardOutlineClearance BoardOutlineClearance_Poly [OnCopper and IsPoly] p2: gap=25 ignorepadtopadclearanceinfootprint=FALSE
BoardOutlineClearance [OnCopper and Not InComponentClass('Logo') and not InComponentClass('FiducialMark') and not InRegion(1000,500,6000,1200) and not InPoly] p3: gap=60 ignorepadtopadclearanceinfootprint=FALSE
Clearance Clearance_magjack [HasFootprint('Pulse_J0B-3563NL')] p1: gap=5 ignorepadtopadclearanceinfootprint=FALSE
Clearance Clearance_2 [InNamedPolygon('BOTTOM_LAYER_BSP_P058')] p2: gap=60 ignorepadtopadclearanceinfootprint=FALSE
Clearance Clearance_1 [InNamedPolygon('TOP_LAYER_BSP_P056')] p3: gap=60 ignorepadtopadclearanceinfootprint=FALSE
Clearance Clearance_Keepouts [((IsTrack Or IsArc) And Not InPoly) And IsFree and IsKeepOut vs ((IsTrack Or IsArc) And Not InPoly) And IsFree and IsKeepOut] p4: gap=0 ignorepadtopadclearanceinfootprint=FALSE
Clearance Clearance_Poly [InPolygon] p5: gap=25 ignorepadtopadclearanceinfootprint=FALSE except(0: Arc-Hole Track-Hole SMDPad-Hole THPad-Hole Via-Hole Fill-Hole Poly-Hole Region-Hole Text-Hole)
Clearance Clearance_FiducialMark [IsKeepOut and InComponentClass('FiducialMark') vs IsPad and InComponentClass('FiducialMark')] p6: gap=0 ignorepadtopadclearanceinfootprint=FALSE
Clearance [All] p7: gap=7 ignorepadtopadclearanceinfootprint=FALSE
ComponentClearance ComponentClearance_MountingHoles_FiducialMarks [InComponentClass('Mounting Holes') vs InComponentClass('FiducialMark')] p1: gap=50 collisioncheckmode=3 verticalgap=10 showdistances=FALSE
ComponentClearance ComponentClearance_Shunt [InComponentClass('Header') vs InComponentClass('Shunt')] p2: gap=0 collisioncheckmode=3 verticalgap=0 showdistances=FALSE
ComponentClearance ComponentClearance_Logo [InComponentClass('Logo')] p3: gap=50 collisioncheckmode=3 verticalgap=10 showdistances=FALSE
ComponentClearance ComponentClearance_ScrewToNut [(HasFootprint('NY PMS 440 0025 PH')) vs (HasFootprint('Keystone_1902C'))] p4: gap=5 collisioncheckmode=3 verticalgap=10 showdistances=FALSE
ComponentClearance ComponentClearance_MountingHoles [InComponentClass('Mounting Holes')] p5: gap=250 collisioncheckmode=3 verticalgap=100000 showdistances=FALSE
ComponentClearance ComponentClearance_SmallPassives [HasFootprint('0201*') or HasFootprint('0402*') or HasFootprint('0508') or HasFootprint('0603*') or HasFootprint('0612') or HasFootprint('0805*') or HasFootprint('0815*') or HasFootprint('0830*') or HasFootprint('1206*') or HasFootprint('1210*') or HasFootprint('1808*') or HasFootprint('1812*') or HasFootprint('1825*') or HasFootprint('2010*') or HasFootprint('2220*') or HasFootprint('2225*') or HasFootprint('2512*') or HasFootprint('2728*') or HasFootprint('3518*') vs HasFootprint('0201*') or HasFootprint('0402*') or HasFootprint('0508') or HasFootprint('0603*') or HasFootprint('0612') or HasFootprint('0805*') or HasFootprint('0815*') or HasFootprint('0830*') or HasFootprint('1206*') or HasFootprint('1210*') or HasFootprint('1808*') or HasFootprint('1812*') or HasFootprint('1825*') or HasFootprint('2010*') or HasFootprint('2220*') or HasFootprint('2225*') or HasFootprint('2512*') or HasFootprint('2728*') or HasFootprint('3518*')] p6: gap=14.96 collisioncheckmode=3 verticalgap=10 showdistances=FALSE
ComponentClearance ComponentClearance_THtoSMT [IsThruComponent vs IsSMTComponent] p7: gap=40 collisioncheckmode=3 verticalgap=30 showdistances=FALSE
ComponentClearance ComponentClearance_THtoTH [IsThruComponent vs IsThruComponent] p8: gap=15 collisioncheckmode=3 verticalgap=30 showdistances=FALSE
ComponentClearance [All] p9: gap=30 collisioncheckmode=3 verticalgap=10 showdistances=FALSE
DiffPairsRouting [All] p1: maxlimit=100 minlimit=10 mostfreqgap=10 toplayer_minwidth=15 toplayer_maxwidth=15 toplayer_prefwidth=15 midlayer1_minwidth=15 midlayer1_maxwidth=15 midlayer1_prefwidth=15 midlayer2_minwidth=15 midlayer2_maxwidth=15 midlayer2_prefwidth=15 midlayer3_minwidth=15 midlayer3_maxwidth=15 midlayer3_prefwidth=15 midlayer4_minwidth=15 midlayer4_maxwidth=15 midlayer4_prefwidth=15 midlayer5_minwidth=15 midlayer5_maxwidth=15 midlayer5_prefwidth=15 midlayer6_minwidth=15 midlayer6_maxwidth=15 midlayer6_prefwidth=15 midlayer7_minwidth=15 midlayer7_maxwidth=15 midlayer7_prefwidth=15 midlayer8_minwidth=15 midlayer8_maxwidth=15 midlayer8_prefwidth=15 bottomlayer_minwidth=15 bottomlayer_maxwidth=15 bottomlayer_prefwidth=15 maxuncoupledlength=1000
FabricationTestPointUsage TestPointUsage [All] p1: valid=2 allowmultiple=FALSE
FabricationTestpoint Testpoint [All] p1: side=3 testpointundercomponent=TRUE minsize=40 maxsize=100 preferedsize=60 minholesize=0 maxholesize=40 preferedholesize=32 testpointgrid=1 allowsidetop=TRUE allowsidebottom=TRUE usegrid=TRUE gridtolerance=0.01
FanoutControl Fanout_LCC [IsLCC] p1: bgadir=Out bgaviamode=Centered fanoutstyle=Auto fanoutdirection=Alternating viagrid=1 // Fanout_LCC (Default Rule)
FanoutControl Fanout_BGA [IsBGA] p2: bgadir=Out bgaviamode=Centered fanoutstyle=Auto fanoutdirection=Alternating viagrid=1 // Fanout_BGA (Default Rule)
FanoutControl Fanout_Default [All] p4: bgadir=Out bgaviamode=Centered fanoutstyle=Auto fanoutdirection=Alternating viagrid=1 // Fanout_Default (Default Rule)
FanoutControl Fanout_Small [(CompPinCount < 5)] p5: bgadir=Out bgaviamode=Centered fanoutstyle=Auto fanoutdirection=OutThenIn viagrid=1 // Fanout_Small (Default Rule)
Height [All] p1: minheight=0 maxheight=1125 prefheight=500
HoleSize [All] p1: absolutevalues=TRUE maxlimit=251 minlimit=7.87 maxpercent=80.000 minpercent=20.000
MinimumAnnularRing MinimumAnnularRing_ThermalPadVias [IsVia and InAnyComponent] p1: minimumring=5.91
MinimumAnnularRing [All] p2: minimumring=5.5
MinimumSolderMaskSliver MinimumSolderMaskSliver_magjack [HasFootprint('Pulse_J0B-3563NL')] p1: minsoldermaskwidth=1
MinimumSolderMaskSliver MinimumSolderMaskSliver_Logo [InComponentClass('Logo') vs InComponentClass('Logo')] p2: minsoldermaskwidth=0.7
MinimumSolderMaskSliver [All] p3: minsoldermaskwidth=3
PlaneConnect [All] p1: planeconnectstyle=Relief reliefexpansion=10 reliefentries=4 reliefconductorwidth=10 reliefairgap=10
PolygonConnect [All] p1: connectstyle=Direct reliefconductorwidth=10 reliefentries=4 polygonreliefangle="90 Angle" airgapwidth=10
RoutingVias ThermalPadVias [IsVia and InAnyComponent] p1: holewidth=7.87 width=19.68 viastyle="Through Hole" minholewidth=7.87 minwidth=19.68 maxholewidth=12.99 maxwidth=23.62
RoutingVias [All] p2: holewidth=16 width=34 viastyle="Through Hole" minholewidth=7.87 minwidth=26 maxholewidth=40 maxwidth=65
SilkToBoardRegionClearance [Not ((IsComment or IsDesignator) And (Hide <> 'False')) and not InRegion(1000,500,4000,800)] p1:
SilkToSilkClearance SilkToSilkClearance_Pb-FreeLogo [(HasFootprint('Pb-Free_Overlay_Medium') OR HasFootprint('Pb-Free_Overlay_Small')) vs (HasFootprint('Pb-Free_Overlay_Medium') OR HasFootprint('Pb-Free_Overlay_Small'))] p1: silktosilkclearance=0
SilkToSilkClearance [All] p2: silktosilkclearance=4
SilkToSolderMaskClearance SilkToComponentPadClearance [(IsPad or IsFill or IsRegion) and InAnycomponent] p1: minsilkscreentomaskgap=3.5 clearancetoexposedcopper=TRUE
SilkToSolderMaskClearance "Silk to Solder Mask Opening" [All] p2: minsilkscreentomaskgap=4 clearancetoexposedcopper=FALSE
SolderMaskExpansion [All] p1: expansion=1.97
Width [All] p1: maxlimit=100 minlimit=7 preferedwidth=10 checkconnectedcopper=TRUE
14 further rules are at their usual default settings.

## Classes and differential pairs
component class PSIL081A_SH4: D34 D35 D36 D37 D38 D39 D40 D41 D42 D43 D44 D45 D46 D47 D48 D49 D50 D51 D52 D53 D54 D55 D56 D57 J55 J56 J57 J58 J59 J60 J61 J62 J63 J64 J65 J66 J67 J68 J69 J70 J71 J72 J73 J74 J75 J76 J77 J78 J79 J80 J81 J82 J83 J84 J85 J86 J87 J88 J89 J90 J91 J92 J93 J94 R73 R74 R75 R76 R77 R78 R79 R80 R81 R82 R83 R84 R85 R86 R87 R88 R89 R90 R91 R92 R93 R94 R95 R96
component class PSIL081A_SH3: D10 D11 D12 D13 D14 D15 D16 D17 D18 D19 D20 D21 D22 D23 D24 D25 D26 D27 D28 D29 D30 D31 D32 D33 J15 J16 J17 J18 J19 J20 J21 J22 J23 J24 J25 J26 J27 J28 J29 J30 J31 J32 J33 J34 J35 J36 J37 J38 J39 J40 J41 J42 J43 J44 J45 J46 J47 J48 J49 J50 J51 J52 J53 J54 R49 R50 R51 R52 R53 R54 R55 R56 R57 R58 R59 R60 R61 R62 R63 R64 R65 R66 R67 R68 R69 R70 R71 R72
component class PSIL081A_SH2: C23 C24 C25 C26 C27 C28 C29 C30 C31 C32 C33 C34 C35 C36 C37 C38 C39 C40 C41 C42 C43 C44 C45 C46 C47 C48 C49 C50 C51 C52 C53 C54 C55 D6 D7 D8 D9 D58 D59 D60 D61 J8 J9 J10 J11 J12 J13 J14 J95 J96 L1 Q5 Q6 Q7 R9 R10 R11 R12 R13 R14 R15 R16 R17 R19 R20 R21 R22 R23 R24 R25 R26 R27 R28 R29 R30 R31 R32 R33 R34 R35 R36 R37 R38 R39 R40 R41 R42 R43 R44 R45 R46 R47 R48 R97 R104 R105 T1 TP4 TP5 TP6 TP7 TP8 TP9 TP10 TP11 TP12 TP13 TP14 U7 U8 U9 U10 U11 U12 U13 U14 U15
component class PSIL081A_SH1: C1 C2 C3 C4 C5 C6 C7 C8 C9 C10 C11 C12 C13 C14 C15 C16 C17 C18 C19 C20 C21 C22 C56 C57 C58 D1 D2 D3 D4 D5 J1 J2 J3 J4 J5 J6 J7 Q1 Q2 Q3 Q4 R1 R2 R3 R4 R5 R6 R7 R8 R18 R98 R99 R100 R101 R102 R103 TP1 TP2 TP3 U1 U2 U3 U4 U5 U6
component class Header: J13 J14 J17 J19 J21 J22 J23 J24 J26 J28 J30 J31 J32 J33 J38 J40 J42 J43 J44 J45 J47 J49 J51 J52 J53 J54 J57 J59 J61 J62 J63 J64 J66 J68 J70 J71 J72 J73 J78 J80 J82 J83 J84 J85 J87 J89 J91 J92 J93 J94
component class AssemblyNote: ZZ2 ZZ3 ZZ4
component class FiducialMark: FID1 FID2 FID3 FID4 FID5 FID6
component class Logo: Logo1
component class PSIL081A_EVM_Hardware: !PCB FID1 FID2 FID3 FID4 FID5 FID6 H1 H2 H3 H4 H5 H6 H7 H8 H9 H10 H11 H12 Logo1 Logo2 Logo3 Logo4 SH-J1 SH-J2 SH-J3 SH-J4 SH-J5 SH-J6 SH-J7 SH-J8 SH-J9 SH-J10 SH-J11 SH-J12 SH-J13 SH-J14 SH-J15 SH-J16 SH-J17 SH-J18 SH-J19 SH-J20 SH-J21 SH-J22 SH-J23 SH-J24 SH-J25 SH-J26 SH-J27 SH-J28 SH-J29 SH-J30 SH-J31 SH-J32 SH-J33 SH-J34 SH-J35 SH-J36 SH-J37 SH-J38 SH-J39 SH-J40 SH-J41 SH-J42 SH-J43 SH-J44 SH-J45 SH-J46 SH-J47 SH-J48 SH-J49 SH-J50 ZZ2 ZZ3 ZZ4
component class Shunt: SH-J1 SH-J2 SH-J3 SH-J4 SH-J5 SH-J6 SH-J7 SH-J8 SH-J9 SH-J10 SH-J11 SH-J12 SH-J13 SH-J14 SH-J15 SH-J16 SH-J17 SH-J18 SH-J19 SH-J20 SH-J21 SH-J22 SH-J23 SH-J24 SH-J25 SH-J26 SH-J27 SH-J28 SH-J29 SH-J30 SH-J31 SH-J32 SH-J33 SH-J34 SH-J35 SH-J36 SH-J37 SH-J38 SH-J39 SH-J40 SH-J41 SH-J42 SH-J43 SH-J44 SH-J45 SH-J46 SH-J47 SH-J48 SH-J49 SH-J50

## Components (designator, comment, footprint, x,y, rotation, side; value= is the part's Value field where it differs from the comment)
C1 "EEV-FK2A470Q" SM_RADIAL_H13 11775,6815 r90 top value=47uF
C2 "885012206046" 0603 10120,6805 r90 top value=0.1uF
C3 "12061C105KAT2A" 1206 10295,7310 r270 top value=1uF
C4 "C2012X7R2A104K125AA" 0805_HV 11930,7405 r90 top value=0.1uF
C5 "885012206046" 0603 9880,7100 r180 top value=0.1uF
C6 "EEV-FK2A470Q" SM_RADIAL_H13 13625,6825 r90 top value=47uF
C7 "GCM188R71C474KA55D" 0603 9605,6740 r270 top value=0.47uF
C8 "GCM188R71C474KA55D" 0603 9730,6855 r0 top value=0.47uF
C9 "12061C105KAT2A" 1206 12150,7310 r270 top value=1uF
C10 "C2012X7R2A104K125AA" 0805_HV 13815,7415 r90 top value=0.1uF
C11 "EEV-FK2A680Q" SM_RADIAL_H13 1305,7520 r180 top value=68uF
C12 "EEV-FK2A680Q" SM_RADIAL_H13 1965,7520 r180 top value=68uF
C13 "EEV-FK2A680Q" SM_RADIAL_H13 2625,7520 r180 top value=68uF
C14 "EEV-FK2A680Q" SM_RADIAL_H13 3285,7520 r180 top value=68uF
C15 "EEV-FK2A680Q" SM_RADIAL_H13 3945,7520 r180 top value=68uF
C16 "EEV-FK2A680Q" SM_RADIAL_H13 4605,7520 r180 top value=68uF
C17 "EEV-FK2A680Q" SM_RADIAL_H13 4605,6950 r180 top value=68uF
C18 "EEV-FK2A680Q" SM_RADIAL_H13 3945,6950 r180 top value=68uF
C19 "EEV-FK2A680Q" SM_RADIAL_H13 3285,6950 r180 top value=68uF
C20 "EEV-FK2A680Q" SM_RADIAL_H13 2625,6950 r180 top value=68uF
C21 "EEV-FK2A680Q" SM_RADIAL_H13 1965,6950 r180 top value=68uF
C22 "EEV-FK2A680Q" SM_RADIAL_H13 1305,6950 r180 top value=68uF
C23 "885012206046" 0603 585,3535 r180 top value=0.1uF
C24 "885012206046" 0603 705,3995 r90 top value=0.1uF
C25 "885012006057" 0603 9745,7430 r0 top value=100pF
C26 "885012006057" 0603 9745,7775 r0 top value=100pF
C27 "885012205044" 0402 10025,7385 r270 top value=1000pF
C28 "885012206046" 0603 9915,7510 r180 top value=0.1uF
C29 "885012205044" 0402 10010,7725 r270 top value=1000pF
C30 "885012206046" 0603 9880,7855 r180 top value=0.1uF
C31 "885012206083" 0603 11040,2980 r90 top value=1000pF
C32 "12061C105KAT2A" 1206 11430,3925 r270 top value=1uF
C33 "C2012X7R2A104K125AA" 0805_HV 11645,3750 r90 top value=0.1uF
C34 "JMK316BJ226ML-T" 1206 11374.63,3188 r180 top value=22uF
C35 "JMK316BJ226ML-T" 1206 11375,3089 r180 top value=22uF
C36 "JMK316BJ226ML-T" 1206 11375,2987 r180 top value=22uF
C37 "C2012X7R2A104K125AA" 0805_HV 10635,3890 r270 top value=0.1uF
C38 "885012205044" 0402 10775,4195 r270 top value=1000pF
C39 "885012206091" 0603 10635,4145 r270 top value=0.022uF
C40 "885012206052" 0603 10755,3845 r0 top value=1uF
C41 "885012005061" 0402 11350,4125 r90 top value=100pF
C42 "885012208041" 1206 11120,3920 r90 top value=10uF
C43 "885012206070" 0603 10645,3710 r0 top value=0.068uF
C44 "885012005061" 0402 10795,2935 r90 top value=100pF
C45 "885012206069" FP-885012206069_0603-MFG 10775,2845 r180 top
C46 "12061C105KAT2A" 1206 7120,7550 r0 top value=1uF
C47 "885012206089" 0603 7505,7640 r90 top value=0.01uF
C48 "JMK316BJ226ML-T" 1206 7350,7670 r90 top value=22uF
C49 "885012206052" 0603 10750,3135 r90 top value=1uF
C50 "C4532X7R3D222K130KA" 1812_HV 11800,3500 r90 top value=2200pF
C51 "C4532X7R3D222K130KA" 1812_HV 10600,3500 r90 top value=2200pF
C52 "EEE-FK1J220P" SM_RADIAL_E 11825,4110 r0 top value=22uF
C53 "C2012X7R2A104K125AA" 0805_HV 11480,4135 r0 top value=0.1uF
C54 "885012206046" 0603 11365,2910 r180 top value=0.1uF
C55 "885012206046" 0603 7715,7450 r180 top value=0.1uF
C56 "C2012X7R2A104K125AA" 0805_HV 11785,7535 r0 top value=0.1uF
C57 "C2012X7R2A104K125AA" 0805_HV 13660,7545 r0 top value=0.1uF
C58 "GCM188R71C105KA64D" 0603 10065,7030 r180 top value=1uF
D1 "SMCJ58A-13-F" SMC 11325,6720 r90 top value=58V
D2 "B3100-13-F" SMC 11325,7335 r90 top value=100V
D3 "BAT54WS-7-F" SOD-323 9740,6945 r180 top value=30V
D4 "SMCJ58A-13-F" SMC 13185,6720 r90 top value=58V
D5 "B3100-13-F" SMC 13175,7335 r90 top value=100V
D6 "B230A-13-F" SMA 11160,3105 r90 top value=30V
D7 "RF071MM2STR" SOD-123F 11590,3620 r180 top value=200V
D8 "MMSD4148T1G" SOD-123 10965,3875 r180 top value=100V
D9 "BAT54S-7-F" SOT-23 10860,3130 r180 top value=30V
D10 "MMSZ5251B-7-F" SOD-123 1084.47,325 r180 bottom value=22V
D11 "MMSZ5251B-7-F" SOD-123 1084.47,825 r180 bottom value=22V
D12 "MMSZ5251B-7-F" SOD-123 5065,700 r0 bottom value=22V
D13 "MMSZ5251B-7-F" SOD-123 1084.47,450 r180 bottom value=22V
D14 "MMSZ5251B-7-F" SOD-123 1084.47,950 r180 bottom value=22V
D15 "MMSZ5251B-7-F" SOD-123 5065,575 r0 bottom value=22V
D16 "MMSZ5251B-7-F" SOD-123 1084.47,1700 r180 bottom value=22V
D17 "MMSZ5251B-7-F" SOD-123 1084.47,1200 r180 bottom value=22V
D18 "MMSZ5251B-7-F" SOD-123 5065,1325 r0 bottom value=22V
D19 "MMSZ5251B-7-F" SOD-123 1084.47,1575 r180 bottom value=22V
D20 "MMSZ5251B-7-F" SOD-123 1084.47,1075 r180 bottom value=22V
D21 "MMSZ5251B-7-F" SOD-123 5065,1450 r0 bottom value=22V
D22 "MMSZ5251B-7-F" SOD-123 1084.47,575 r180 bottom value=22V
D23 "MMSZ5251B-7-F" SOD-123 5065,950 r0 bottom value=22V
D24 "MMSZ5251B-7-F" SOD-123 5065,450 r0 bottom value=22V
D25 "MMSZ5251B-7-F" SOD-123 1084.47,700 r180 bottom value=22V
D26 "MMSZ5251B-7-F" SOD-123 5065,825 r0 bottom value=22V
D27 "MMSZ5251B-7-F" SOD-123 5065,325 r0 bottom value=22V
D28 "MMSZ5251B-7-F" SOD-123 1084.47,1450 r180 bottom value=22V
D29 "MMSZ5251B-7-F" SOD-123 5065,1075 r0 bottom value=22V
D30 "MMSZ5251B-7-F" SOD-123 5065,1575 r0 bottom value=22V
D31 "MMSZ5251B-7-F" SOD-123 1084.47,1325 r180 bottom value=22V
D32 "MMSZ5251B-7-F" SOD-123 5065,1200 r0 bottom value=22V
D33 "MMSZ5251B-7-F" SOD-123 5065,1700 r0 bottom value=22V
D34 "MMSZ5251B-7-F" SOD-123 6035,325 r180 bottom value=22V
D35 "MMSZ5251B-7-F" SOD-123 6035,825 r180 bottom value=22V
D36 "MMSZ5251B-7-F" SOD-123 10015,700 r0 bottom value=22V
D37 "MMSZ5251B-7-F" SOD-123 6035,450 r180 bottom value=22V
D38 "MMSZ5251B-7-F" SOD-123 6035,950 r180 bottom value=22V
D39 "MMSZ5251B-7-F" SOD-123 10015,575 r0 bottom value=22V
D40 "MMSZ5251B-7-F" SOD-123 6035,1700 r180 bottom value=22V
D41 "MMSZ5251B-7-F" SOD-123 6035,1200 r180 bottom value=22V
D42 "MMSZ5251B-7-F" SOD-123 10015,1325 r0 bottom value=22V
D43 "MMSZ5251B-7-F" SOD-123 6035,1575 r180 bottom value=22V
D44 "MMSZ5251B-7-F" SOD-123 6035,1075 r180 bottom value=22V
D45 "MMSZ5251B-7-F" SOD-123 10015,1450 r0 bottom value=22V
D46 "MMSZ5251B-7-F" SOD-123 6035,575 r180 bottom value=22V
D47 "MMSZ5251B-7-F" SOD-123 10015,950 r0 bottom value=22V
D48 "MMSZ5251B-7-F" SOD-123 10015,450 r0 bottom value=22V
D49 "MMSZ5251B-7-F" SOD-123 6035,700 r180 bottom value=22V
D50 "MMSZ5251B-7-F" SOD-123 10015,825 r0 bottom value=22V
D51 "MMSZ5251B-7-F" SOD-123 10015,325 r0 bottom value=22V
D52 "MMSZ5251B-7-F" SOD-123 6035,1450 r180 bottom value=22V
D53 "MMSZ5251B-7-F" SOD-123 10015,1075 r0 bottom value=22V
D54 "MMSZ5251B-7-F" SOD-123 10015,1575 r0 bottom value=22V
D55 "MMSZ5251B-7-F" SOD-123 6035,1325 r180 bottom value=22V
D56 "MMSZ5251B-7-F" SOD-123 10015,1200 r0 bottom value=22V
D57 "MMSZ5251B-7-F" SOD-123 10015,1700 r0 bottom value=22V
D58 "BAT54WS-7-F" SOD-323 555,3960 r90 top value=30V
D59 "BAT54WS-7-F" SOD-323 555,3640 r270 top value=30V
D60 "BAT54WS-7-F" SOD-323 13420,4050 r180 top value=30V
D61 "BAT54WS-7-F" SOD-323 13420,4150 r180 top value=30V
FID1 "Fiducial" Fiducial10-20 50,7950 r0 top
FID2 "Fiducial" Fiducial10-20 13950,7950 r0 top
FID3 "Fiducial" Fiducial10-20 50,50 r0 top
FID4 "Fiducial" Fiducial10-20 50,7950 r180 bottom
FID5 "Fiducial" Fiducial10-20 13950,7950 r180 bottom
FID6 "Fiducial" Fiducial10-20 50,50 r180 bottom
H1 "SJ61A6" 3M_SJ61A6 9600,4850 r180 bottom
H2 "SJ61A6" 3M_SJ61A6 13600,7650 r180 bottom
H3 "SJ61A6" 3M_SJ61A6 13500,300 r180 bottom
H4 "SJ61A6" 3M_SJ61A6 5150,4850 r180 bottom
H5 "SJ61A6" 3M_SJ61A6 3650,1950 r180 bottom
H6 "SJ61A6" 3M_SJ61A6 8600,1950 r180 bottom
H7 "SJ61A6" 3M_SJ61A6 350,7650 r180 bottom
H8 "SJ61A6" 3M_SJ61A6 300,300 r180 bottom
H9 "SJ61A6" 3M_SJ61A6 300,3100 r180 bottom
H10 "SJ61A6" 3M_SJ61A6 13600,3150 r180 bottom
H11 "SJ61A6" 3M_SJ61A6 5150,7650 r180 bottom
H12 "SJ61A6" 3M_SJ61A6 9350,7650 r180 bottom
J1 "1723161310" Molex_1723161310 10775,7470 r180 top
J2 "1723161310" Molex_1723161310 535,6000 r270 top
J3 "1723161310" Molex_1723161310 12625,7470 r180 top
J4 "1723161310" Molex_1723161310 535,5150 r270 top
J5 "SSW-112-21-G-D" Samtec_SSW-112-01-x-D 2975,6150 r180 top locked
J6 "1723161310" Molex_1723161310 13465,6000 r90 top
J7 "1723161310" Molex_1723161310 13465,5150 r90 top
J8 "TST-107-01-G-D" Samtec_TST-107-01-G-D 250,3950 r180 top
J9 "TST-107-01-G-D" Samtec_TST-107-01-G-D 13750,3950 r0 top
J10 "N2510-6002-RB" CONN_2510-6002 8350,7650 r0 top
J11 "SSW-110-21-G-S" CONN_SSW-110-23-F-S 8225,6200 r0 top locked
J12 "SSW-112-21-G-S" Samtec_SSW-112-21-x-S 12250,2500 r0 top locked
J13 "TSW-102-07-G-S" TSW-102-07-G-S 11220,2800 r0 top
J14 "TSW-103-07-G-S" TSW-103-07-G-S 7450,7450 r180 top
J15 "J0B-3563NL" Pulse_J0B-3563NL 3070,290 r90 top locked
J16 "SS-7188V-A-NF" CONN_SS-7188V-A-NF 1260,2310 r0 top
J17 "TSW-102-07-G-S" TSW-102-07-G-S 750,325 r180 top
J18 "SS-7188V-A-NF" CONN_SS-7188V-A-NF 2810,2305 r0 top
J19 "TSW-102-07-G-S" TSW-102-07-G-S 750,825 r180 top
J20 "SS-7188V-A-NF" CONN_SS-7188V-A-NF 4355,2305 r0 top
J21 "TSW-102-07-G-S" TSW-102-07-G-S 5400,700 r0 top
J22 "TSW-102-07-G-S" TSW-102-07-G-S 750,450 r180 top
J23 "TSW-102-07-G-S" TSW-102-07-G-S 750,950 r180 top
J24 "TSW-102-07-G-S" TSW-102-07-G-S 5400,575 r0 top
J25 "SS-7188V-A-NF" CONN_SS-7188V-A-NF 1260,3005 r0 top
J26 "TSW-102-07-G-S" TSW-102-07-G-S 750,1700 r180 top
J27 "SS-7188V-A-NF" CONN_SS-7188V-A-NF 2810,3000 r0 top
J28 "TSW-102-07-G-S" TSW-102-07-G-S 750,1200 r180 top
J29 "SS-7188V-A-NF" CONN_SS-7188V-A-NF 4355,3000 r0 top
J30 "TSW-102-07-G-S" TSW-102-07-G-S 5400,1325 r0 top
J31 "TSW-102-07-G-S" TSW-102-07-G-S 750,1575 r180 top
J32 "TSW-102-07-G-S" TSW-102-07-G-S 750,1075 r180 top
J33 "TSW-102-07-G-S" TSW-102-07-G-S 5400,1450 r0 top
J34 "SSW-108-21-G-D" Samtec_SSW-108-01-x-D 1925,3900 r0 top locked
J35 "SSW-108-21-G-D" Samtec_SSW-108-01-x-D 3375,3900 r0 top locked
J36 "SSW-108-21-G-D" Samtec_SSW-108-01-x-D 4825,3900 r0 top locked
J37 "SS-7188V-A-NF" CONN_SS-7188V-A-NF 2035,2305 r0 top
J38 "TSW-102-07-G-S" TSW-102-07-G-S 750,575 r180 top
J39 "SS-7188V-A-NF" CONN_SS-7188V-A-NF 3585,2305 r0 top
J40 "TSW-102-07-G-S" TSW-102-07-G-S 5400,950 r0 top
J41 "SS-7188V-A-NF" CONN_SS-7188V-A-NF 5135,2305 r0 top
J42 "TSW-102-07-G-S" TSW-102-07-G-S 5400,450 r0 top
J43 "TSW-102-07-G-S" TSW-102-07-G-S 750,700 r180 top
J44 "TSW-102-07-G-S" TSW-102-07-G-S 5400,825 r0 top
J45 "TSW-102-07-G-S" TSW-102-07-G-S 5400,325 r0 top
J46 "SS-7188V-A-NF" CONN_SS-7188V-A-NF 2035,3000 r0 top
J47 "TSW-102-07-G-S" TSW-102-07-G-S 750,1450 r180 top
J48 "SS-7188V-A-NF" CONN_SS-7188V-A-NF 3585,3000 r0 top
J49 "TSW-102-07-G-S" TSW-102-07-G-S 5400,1075 r0 top
J50 "SS-7188V-A-NF" CONN_SS-7188V-A-NF 5135,3000 r0 top
J51 "TSW-102-07-G-S" TSW-102-07-G-S 5400,1575 r0 top
J52 "TSW-102-07-G-S" TSW-102-07-G-S 750,1325 r180 top
J53 "TSW-102-07-G-S" TSW-102-07-G-S 5400,1200 r0 top
J54 "TSW-102-07-G-S" TSW-102-07-G-S 5400,1700 r0 top
J55 "J0B-3563NL" Pulse_J0B-3563NL 8030,290 r90 top locked
J56 "SS-7188V-A-NF" CONN_SS-7188V-A-NF 5960,2310 r0 top
J57 "TSW-102-07-G-S" TSW-102-07-G-S 5700,325 r180 top
J58 "SS-7188V-A-NF" CONN_SS-7188V-A-NF 7510,2310 r0 top
J59 "TSW-102-07-G-S" TSW-102-07-G-S 5700,825 r180 top
J60 "SS-7188V-A-NF" CONN_SS-7188V-A-NF 9055,2310 r0 top
J61 "TSW-102-07-G-S" TSW-102-07-G-S 10350,700 r0 top
J62 "TSW-102-07-G-S" TSW-102-07-G-S 5700,450 r180 top
J63 "TSW-102-07-G-S" TSW-102-07-G-S 5700,950 r180 top
J64 "TSW-102-07-G-S" TSW-102-07-G-S 10350,575 r0 top
J65 "SS-7188V-A-NF" CONN_SS-7188V-A-NF 5960,3005 r0 top
J66 "TSW-102-07-G-S" TSW-102-07-G-S 5700,1700 r180 top
J67 "SS-7188V-A-NF" CONN_SS-7188V-A-NF 7510,3005 r0 top
J68 "TSW-102-07-G-S" TSW-102-07-G-S 5700,1200 r180 top
J69 "SS-7188V-A-NF" CONN_SS-7188V-A-NF 9055,3005 r0 top
J70 "TSW-102-07-G-S" TSW-102-07-G-S 10350,1325 r0 top
J71 "TSW-102-07-G-S" TSW-102-07-G-S 5700,1575 r180 top
J72 "TSW-102-07-G-S" TSW-102-07-G-S 5700,1075 r180 top
J73 "TSW-102-07-G-S" TSW-102-07-G-S 10350,1450 r0 top
J74 "SSW-108-21-G-D" Samtec_SSW-108-01-x-D 6275,3900 r0 top locked
J75 "SSW-108-21-G-D" Samtec_SSW-108-01-x-D 7725,3900 r0 top locked
J76 "SSW-108-21-G-D" Samtec_SSW-108-01-x-D 9175,3900 r0 top locked
J77 "SS-7188V-A-NF" CONN_SS-7188V-A-NF 6735,2310 r0 top
J78 "TSW-102-07-G-S" TSW-102-07-G-S 5700,575 r180 top
J79 "SS-7188V-A-NF" CONN_SS-7188V-A-NF 8285,2310 r0 top
J80 "TSW-102-07-G-S" TSW-102-07-G-S 10350,950 r0 top
J81 "SS-7188V-A-NF" CONN_SS-7188V-A-NF 9835,2310 r0 top
J82 "TSW-102-07-G-S" TSW-102-07-G-S 10350,450 r0 top
J83 "TSW-102-07-G-S" TSW-102-07-G-S 5700,700 r180 top
J84 "TSW-102-07-G-S" TSW-102-07-G-S 10350,825 r0 top
J85 "TSW-102-07-G-S" TSW-102-07-G-S 10350,325 r0 top
J86 "SS-7188V-A-NF" CONN_SS-7188V-A-NF 6735,3005 r0 top
J87 "TSW-102-07-G-S" TSW-102-07-G-S 5700,1450 r180 top
J88 "SS-7188V-A-NF" CONN_SS-7188V-A-NF 8285,3005 r0 top
J89 "TSW-102-07-G-S" TSW-102-07-G-S 10350,1075 r0 top
J90 "SS-7188V-A-NF" CONN_SS-7188V-A-NF 9835,3005 r0 top
J91 "TSW-102-07-G-S" TSW-102-07-G-S 10350,1575 r0 top
J92 "TSW-102-07-G-S" TSW-102-07-G-S 5700,1325 r180 top
J93 "TSW-102-07-G-S" TSW-102-07-G-S 10350,1200 r0 top
J94 "TSW-102-07-G-S" TSW-102-07-G-S 10350,1700 r0 top
J95 "SSW-112-21-G-S" Samtec_SSW-112-21-x-S 10700,850 r90 top locked
J96 "SSW-112-21-G-S" Samtec_SSW-112-21-x-S 13800,850 r270 top locked
L1 "74438323033" WE-MAPI_2510 11550,3910 r270 top value=3.3uH
Logo1 "Texas Instruments" TI_Stacked_Overlay_Small 5475,7785 r0 top
Logo2 "CE Mark" CE_Mark_5mm 5632.4,7320 r0 top
Logo3 "FCC disclaimer" FCC_disclaimer 5761.99,7071.18 r0 top
Logo4 "WEEE logo" WEEE_Minimum 5234.36,7361.38 r0 top
Q1 "CSD19536KTT" KTT0002A 10950,6785 r270 top value=100V
Q2 "CSD19536KTT" KTT0002A 10450,6785 r270 top value=100V
Q3 "CSD19536KTT" KTT0002A 12800,6785 r270 top value=100V
Q4 "CSD19536KTT" KTT0002A 12300,6785 r270 top value=100V
Q5 "MMBT3904LT1G" SOT-23 9595,7390 r180 top value="40 V"
Q6 "MMBT3904LT1G" SOT-23 9590,7740 r180 top value="40 V"
Q7 "BSZ900N15NS3 G" PG-TSDSON-8 11260,3910 r270 top value=150V
R1 "CRCW0603100RJNEA" 0603 11930,7260 r270 top value=100
R2 "CRCW04021K00FKED" 0402 9460,6750 r90 top value=1.00k
R3 "CRCW04023K01FKED" 0402 9000,6860 r0 top value=3.01k
R4 "HCS2512FTL500" HCS_2512_122 10010,6520 r0 top value=0.0005
R5 "CRCW040240K2FKED" 0402 9730,7015 r180 top value=40.2k
R6 "CRCW0603100RJNEA" 0603 13815,7270 r270 top value=100
R7 "CRCW040210K0FKED" 0402 9875,6780 r0 top value=10.0k
R8 "CRCW04026K65FKED" 0402 9875,6835 r0 top value=6.65k
R9 "CRCW040210K0FKED" 0402 625,3940 r270 top value=10.0k
R10 "CRCW040210K0FKED" 0402 625,3630 r90 top value=10.0k
R11 "CRCW040210K0FKED" 0402 890,3610 r90 top value=10.0k
R12 "CRCW040210K0FKED" 0402 975,3665 r90 top value=10.0k
R13 "CRCW040210K0FKED" 0402 800,3900 r0 top value=10.0k
R14 "ERJ-2GE0R00X" 0402 800,3845 r180 top value=0
R15 "ERJ-2GE0R00X" 0402 745,3585 r180 top value=0
R16 "CRCW040249R9FKED" 0402 530,3750 r0 top value=49.9
R17 "CRCW040249R9FKED" 0402 530,3850 r0 top value=49.9
R18 "ERJ-2GE0R00X" 0402 9970,7005 r90 top value=0
R19 "CRCW04024K99FKED" 0402 9680,7290 r0 top value=4.99k
R20 "CRCW04021K00FKED" 0402 9570,7290 r180 top value=1.00k
R21 "CRCW04023K01FKED" 0402 9000,7290 r0 top value=3.01k
R22 "CRCW04024K99FKED" 0402 9675,7640 r0 top value=4.99k
R23 "CRCW04021K00FKED" 0402 9565,7640 r180 top value=1.00k
R24 "CRCW04023K01FKED" 0402 9000,7640 r0 top value=3.01k
R25 "CRCW0402200KFKED" 0402 9880,7355 r0 top value=200k
R26 "CRCW0402200KFKED" 0402 9870,7700 r0 top value=200k
R27 "CRCW04025K36FKED" 0402 9970,7385 r90 top value=5.36k
R28 "CRCW04025K36FKED" 0402 9955,7725 r90 top value=5.36k
R29 "CRCW080551R0JNEA" 0805_HV 11040,3125 r270 top value=51
R30 "CRCW080539K0JNEA" 0805_HV 11550,3750 r270 top value=39k
R31 "CRCW040210R0JNED" 0402 10635,4025 r270 top value=10
R32 "CRCW0402100KFKED" 0402 10885,4195 r270 top value=100k
R33 "CRCW080520R0JNEA" 0805_HV 10920,3725 r90 top value=20
R34 "CRCW040210R0JNED" 0402 11200,4065 r270 top value=10
R35 "CRCW04021K00FKED" 0402 11285,4125 r270 top value=1.00k
R36 "CRCW04023K57FKED" 0402 10830,4195 r90 top value=3.57k
R37 "CRCW040225K5FKED" 0402 10720,4195 r90 top value=25.5k
R38 "CRCW06031R74FKEA" 0603 11315,4030 r0 top value=1.74
R39 "ERJ-2GE0R00X" 0402 10775,2730 r0 top value=0
R40 "CRCW04021K50FKED" 0402 10640,3775 r0 top value=1.50k
R41 "CRCW0402237RFKED" 0402 10725,3310 r90 top value=237
R42 "CRCW040210K0FKED" 0402 10830,3230 r180 top value=10.0k
R43 "CRCW040210K0FKED" 0402 10775,2785 r0 top value=10.0k
R44 "ERJ-2GE0R00X" 0402 10740,2935 r90 top value=0
R45 "CRCW04021K00FKED" 0402 10805,3335 r180 top value=1.00k
R46 "CRCW0402100KFKED" 0402 7430,7630 r90 top value=100k
R47 "CRCW04025K90FKED" 0402 10910,2845 r0 top value=5.90k
R48 "CRCW040254K9FKED" 0402 7430,7735 r90 top value=54.9k
R49 "CRCW060335K7FKEA" 0603 924.47,325 r180 bottom value=35.7k
R50 "CRCW060335K7FKEA" 0603 924.47,825 r180 bottom value=35.7k
R51 "CRCW060335K7FKEA" 0603 5225,700 r0 bottom value=35.7k
R52 "CRCW060335K7FKEA" 0603 924.47,450 r0 bottom value=35.7k
R53 "CRCW060335K7FKEA" 0603 924.47,950 r0 bottom value=35.7k
R54 "CRCW060335K7FKEA" 0603 5225,575 r180 bottom value=35.7k
R55 "CRCW060335K7FKEA" 0603 924.47,1700 r180 bottom value=35.7k
R56 "CRCW060335K7FKEA" 0603 924.47,1200 r180 bottom value=35.7k
R57 "CRCW060335K7FKEA" 0603 5225,1325 r0 bottom value=35.7k
R58 "CRCW060335K7FKEA" 0603 924.47,1575 r0 bottom value=35.7k
R59 "CRCW060335K7FKEA" 0603 924.47,1075 r0 bottom value=35.7k
R60 "CRCW060335K7FKEA" 0603 5225,1450 r180 bottom value=35.7k
R61 "CRCW060335K7FKEA" 0603 924.47,575 r180 bottom value=35.7k
R62 "CRCW060335K7FKEA" 0603 5225,950 r0 bottom value=35.7k
R63 "CRCW060335K7FKEA" 0603 5225,450 r0 bottom value=35.7k
R64 "CRCW060335K7FKEA" 0603 924.47,700 r0 bottom value=35.7k
R65 "CRCW060335K7FKEA" 0603 5225,825 r180 bottom value=35.7k
R66 "CRCW060335K7FKEA" 0603 5225,325 r180 bottom value=35.7k
R67 "CRCW060335K7FKEA" 0603 924.47,1450 r180 bottom value=35.7k
R68 "CRCW060335K7FKEA" 0603 5225,1075 r0 bottom value=35.7k
R69 "CRCW060335K7FKEA" 0603 5225,1575 r0 bottom value=35.7k
R70 "CRCW060335K7FKEA" 0603 924.47,1325 r0 bottom value=35.7k
R71 "CRCW060335K7FKEA" 0603 5225,1200 r180 bottom value=35.7k
R72 "CRCW060335K7FKEA" 0603 5225,1700 r180 bottom value=35.7k
R73 "CRCW060335K7FKEA" 0603 5875,325 r180 bottom value=35.7k
R74 "CRCW060335K7FKEA" 0603 5875,825 r180 bottom value=35.7k
R75 "CRCW060335K7FKEA" 0603 10175,700 r0 bottom value=35.7k
R76 "CRCW060335K7FKEA" 0603 5875,450 r0 bottom value=35.7k
R77 "CRCW060335K7FKEA" 0603 5875,950 r0 bottom value=35.7k
R78 "CRCW060335K7FKEA" 0603 10175,575 r180 bottom value=35.7k
R79 "CRCW060335K7FKEA" 0603 5875,1700 r180 bottom value=35.7k
R80 "CRCW060335K7FKEA" 0603 5875,1200 r180 bottom value=35.7k
R81 "CRCW060335K7FKEA" 0603 10175,1325 r0 bottom value=35.7k
R82 "CRCW060335K7FKEA" 0603 5875,1575 r0 bottom value=35.7k
R83 "CRCW060335K7FKEA" 0603 5875,1075 r0 bottom value=35.7k
R84 "CRCW060335K7FKEA" 0603 10175,1450 r180 bottom value=35.7k
R85 "CRCW060335K7FKEA" 0603 5875,575 r180 bottom value=35.7k
R86 "CRCW060335K7FKEA" 0603 10175,950 r0 bottom value=35.7k
R87 "CRCW060335K7FKEA" 0603 10175,450 r0 bottom value=35.7k
R88 "CRCW060335K7FKEA" 0603 5875,700 r0 bottom value=35.7k
R89 "CRCW060335K7FKEA" 0603 10180,825 r180 bottom value=35.7k
R90 "CRCW060335K7FKEA" 0603 10175,325 r180 bottom value=35.7k
R91 "CRCW060335K7FKEA" 0603 5875,1450 r180 bottom value=35.7k
R92 "CRCW060335K7FKEA" 0603 10175,1075 r0 bottom value=35.7k
R93 "CRCW060335K7FKEA" 0603 10175,1575 r0 bottom value=35.7k
R94 "CRCW060335K7FKEA" 0603 5875,1325 r0 bottom value=35.7k
R95 "CRCW060335K7FKEA" 0603 10175,1200 r180 bottom value=35.7k
R96 "CRCW060335K7FKEA" 0603 10175,1700 r180 bottom value=35.7k
R97 "ERJ-2GE0R00X" 0402 8350,7375 r90 top value=0
R98 "CRCW060310R0JNEA" 0603 11605,7380 r0 top value=10
R99 "CRCW060310R0JNEA" 0603 11605,7450 r180 top value=10
R100 "CRCW060310R0JNEA" 0603 11775,7295 r180 top value=10
R101 "CRCW060310R0JNEA" 0603 13480,7390 r0 top value=10
R102 "CRCW060310R0JNEA" 0603 13480,7460 r0 top value=10
R103 "CRCW060310R0JNEA" 0603 13650,7300 r180 top value=10
R104 "ERJ-2GE0R00X" 0402 9485,7458 r0 top value=0
R105 "ERJ-2GE0R00X" 0402 9485,7829 r0 top value=0
SH-J1 "SPC02SYAN" SPC02SYAN 5399,702 r180 top value=1x2
SH-J2 "SPC02SYAN" SPC02SYAN 5399,575 r180 top value=1x2
SH-J3 "SPC02SYAN" SPC02SYAN 5401,450.5 r180 top value=1x2
SH-J4 "SPC02SYAN" SPC02SYAN 5400.33,325 r180 top value=1x2
SH-J5 "SPC02SYAN" SPC02SYAN 752,1700 r180 top value=1x2
SH-J6 "SPC02SYAN" SPC02SYAN 749.76,1575 r180 top value=1x2
SH-J7 "SPC02SYAN" SPC02SYAN 749.76,1451 r180 top value=1x2
SH-J8 "SPC02SYAN" SPC02SYAN 747.81,1325 r180 top value=1x2
SH-J9 "SPC02SYAN" SPC02SYAN 750,1200 r180 top value=1x2
SH-J10 "SPC02SYAN" SPC02SYAN 749,1075.46 r180 top value=1x2
SH-J11 "SPC02SYAN" SPC02SYAN 752,951 r180 top value=1x2
SH-J12 "SPC02SYAN" SPC02SYAN 749,825 r180 top value=1x2
SH-J13 "SPC02SYAN" SPC02SYAN 752,700 r180 top value=1x2
SH-J14 "SPC02SYAN" SPC02SYAN 749,576 r180 top value=1x2
SH-J15 "SPC02SYAN" SPC02SYAN 749,449 r180 top value=1x2
SH-J16 "SPC02SYAN" SPC02SYAN 749,324 r180 top value=1x2
SH-J17 "SPC02SYAN" SPC02SYAN 5699,1201 r180 top value=1x2
SH-J18 "SPC02SYAN" SPC02SYAN 5699,1076 r180 top value=1x2
SH-J19 "SPC02SYAN" SPC02SYAN 5699,950 r180 top value=1x2
SH-J20 "SPC02SYAN" SPC02SYAN 5697,824.31 r180 top value=1x2
SH-J21 "SPC02SYAN" SPC02SYAN 5700,699 r180 top value=1x2
SH-J22 "SPC02SYAN" SPC02SYAN 5701,574.5 r180 top value=1x2
SH-J23 "SPC02SYAN" SPC02SYAN 5696,325.46 r180 top value=1x2
SH-J24 "SPC02SYAN" SPC02SYAN 5700,450.5 r180 top value=1x2
SH-J25 "SPC02SYAN" SPC02SYAN 5399,1701 r180 top value=1x2
SH-J26 "SPC02SYAN" SPC02SYAN 5399,1574 r180 top value=1x2
SH-J27 "SPC02SYAN" SPC02SYAN 5399,1449.84 r180 top value=1x2
SH-J28 "SPC02SYAN" SPC02SYAN 5400.33,1325.46 r180 top value=1x2
SH-J29 "SPC02SYAN" SPC02SYAN 5397,1201 r180 top value=1x2
SH-J30 "SPC02SYAN" SPC02SYAN 5400.33,1076.1 r180 top value=1x2
SH-J31 "SPC02SYAN" SPC02SYAN 5399,950 r180 top value=1x2
SH-J32 "SPC02SYAN" SPC02SYAN 5397,826 r180 top value=1x2
SH-J33 "SPC02SYAN" SPC02SYAN 10350,1700 r180 top value=1x2
SH-J34 "SPC02SYAN" SPC02SYAN 10350,1576 r180 top value=1x2
SH-J35 "SPC02SYAN" SPC02SYAN 10351,1452 r180 top value=1x2
SH-J36 "SPC02SYAN" SPC02SYAN 10351,1327 r180 top value=1x2
SH-J37 "SPC02SYAN" SPC02SYAN 10350,1202 r180 top value=1x2
SH-J38 "SPC02SYAN" SPC02SYAN 10348,1077.04 r180 top value=1x2
SH-J39 "SPC02SYAN" SPC02SYAN 10349,951 r180 top value=1x2
SH-J40 "SPC02SYAN" SPC02SYAN 10350,827 r180 top value=1x2
SH-J41 "SPC02SYAN" SPC02SYAN 10351,700 r180 top value=1x2
SH-J42 "SPC02SYAN" SPC02SYAN 10349,324.96 r180 top value=1x2
SH-J43 "SPC02SYAN" SPC02SYAN 10350,574.5 r180 top value=1x2
SH-J44 "SPC02SYAN" SPC02SYAN 10350,450 r180 top value=1x2
SH-J45 "SPC02SYAN" SPC02SYAN 5702,1700 r180 top value=1x2
SH-J46 "SPC02SYAN" SPC02SYAN 5700,1575 r180 top value=1x2
SH-J47 "SPC02SYAN" SPC02SYAN 5700,1451 r180 top value=1x2
SH-J48 "SPC02SYAN" SPC02SYAN 5700,1326.1 r180 top value=1x2
SH-J49 "SPC02SYAN" SPC02SYAN 11212.02,2800 r180 top value=1x2
SH-J50 "SPC02SYAN" SPC02SYAN 7502,7450 r180 top value=1x2
T1 "749119133" Wurth_EP11_5 11235,3525 r270 top value=400uH
TP1 "55VDC" Keystone5000 12955,5720 r90 top
TP2 "GND" Keystone5001 12955,5425 r90 top
TP3 "OC_ALERT" Keystone5004 8750,6850 r90 top
TP4 "SDA" Keystone5002 8250,6850 r90 top
TP5 "SCL" Keystone5002 8475,7125 r90 top
TP6 "PG1" Keystone5003 8750,7125 r90 top
TP7 "PG2" Keystone5003 8750,7350 r90 top
TP8 "PSE_3.3V" Keystone5000 7750,7600 r90 top
TP9 "GND" Keystone5001 7750,7795 r90 top
TP10 "3.3V_ISO" Keystone5000 11650,2800 r90 top
TP11 "3.3V" Keystone5000 7600,7800 r90 top
TP12 "GND_ISO" Keystone5001 11760,3110 r90 top
TP13 "GND_ISO" Keystone5001 8250,7125 r90 top
TP14 "OSS" Keystone5002 8475,6850 r90 top
U1 "INA240A2PWR" PW0008A_L 10010,6805 r90 top
U2 "FOD817DS" N04C 9280,6910 r180 top
U3 "LM5050MK-1/NOPB" DDC0006A_N 11795,7410 r180 top
U4 "TLV7021DCKR" DCK0005A_N 9880,6985 r90 top
U5 "REF3425IDBVR" DBV0006A_N 9730,6740.31 r0 top
U6 "LM5050MK-1/NOPB" DDC0006A_N 13670,7415 r180 top
U7 "TCA9517ADGKR" DGK0008A_N 800,3740 r0 top
U8 "TLV431AIDBVR" DBV0005A_N 10900,2970 r270 top
U9 "TPS389001DSER" DSE0006A 9890,7430 r180 top
U10 "FOD817DS" N04C 9280,7340 r180 top
U11 "TPS389001DSER" DSE0006A 9880,7775 r180 top
U12 "FOD817DS" N04C 9280,7690 r180 top
U13 "LM5020MM-1/NOPB" DGS0010A_N 10755,4010 r90 top
U14 "TPS7A4001DGNR" DGN0008B_N 7175,7680 r180 top
U15 "HMHA2801A" MFP04A 10805,3525 r90 top
ZZ2 "These assemblies are ESD sensitive, ESD precautions shall be observed." AssemblyNote 150,8575 r0 top
ZZ3 "These assemblies must be clean and free from flux and all contaminants. Use of no clean flux is not acceptable." AssemblyNote 160,8385 r0 top
ZZ4 "These assemblies must comply with workmanship standards IPC-A-610 Class 2, unless otherwise specified." AssemblyNote 175,8235 r0 top

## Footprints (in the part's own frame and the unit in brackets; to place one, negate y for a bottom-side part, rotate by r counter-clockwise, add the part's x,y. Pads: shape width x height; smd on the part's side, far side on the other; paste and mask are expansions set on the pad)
3M_SJ61A6 [mil] "BUMPER CYLIN 0.312\" DIA"
  body extent -156,-156 156,156, height 195
0402 [mm] "0402 from SM-752 data"
  rect 0.8x0.6 smd: 1(-0.6,0) 2(0.6,0)
  silkscreen extent -1.22,-0.52 1.22,0.52, body extent -0.55,-0.3 0.55,0.3, height 0.6
0603 [mm] "0603 from SM-752 data"
  rect 1x0.95 smd: 1(-0.8,0) 2(0.8,0)
  silkscreen extent -1.52,-0.69 1.52,0.69, body extent -0.87,-0.47 0.87,0.47, height 1
0805_HV [mil] "0805 with 30mil clearance between pads"
  rect 50x63 smd: 1(-40,0) 2(40,0)
  silkscreen extent -74,-40 74,40, body extent -43,-29 43,29, height 57
1206 [mm] "1206 from SM-752 data"
  rect 1.3x1.85 smd: 1(-1.45,0) 2(1.45,0)
  silkscreen extent -2.4,-1.21 2.4,1.21, body extent -1.7,-0.9 1.7,0.9, height 1.35
1812_HV [mil] "PRG recommended land pattern"
  rect 60x140 smd: 1(-85,0) 2(85,0)
  silkscreen extent -129,-84 129,84, body extent -94,-67 94,67, height 53
AssemblyNote [mil] "Assembly Note"
CE_Mark_5mm [mil] "Minimum text height for CE Mark"
  silkscreen extent -138,-98 138,98
CONN_2510-6002 [mm] "3M 2500 series TS-0770-L December 15, 2011"
  rect 1.65x1.65 hole 1.016 mask+0: 1(-5.08,-1.27)
  round 1.65 hole 1.016 mask+0: 2(-5.08,1.27) 3(-2.54,-1.27) 4(-2.54,1.27) 5(0,-1.27) 6(0,1.27) 7(2.54,-1.27) 8(2.54,1.27) 9(5.08,-1.27) 10(5.08,1.27)
  silkscreen extent -10.01,-4.17 10.01,4.47, body extent -10.01,-4.11 10.01,4.52, height 9.92
CONN_SS-7188V-A-NF [mm] "Connector; PCB Jack, Thru-Hole; 1-Port, 8 Pos, Unshielded"
  rect 1.4x1.4 hole 0.89: 1(-4.445,6.35)
  round 1.4 hole 0.89: 2(-3.175,8.89) 3(-1.905,6.35) 4(-0.635,8.89) 5(0.635,6.35) 6(1.905,8.89) 7(3.175,6.35) 8(4.445,8.89)
  round 1.524 hole 3.251 unplated: MH1(-5.715,0) MH2(5.715,0)
  silkscreen extent -7.87,-6.48 8.13,9.91, body extent -7.75,-6.35 8,9.78, height 13.34
CONN_SSW-110-23-F-S [mm] "SAMTEC"
  rect 1.65x1.65 hole 1.15: 1(11.43,0)
  round 1.65 hole 1.15: 2(8.89,0) 3(6.35,0) 4(3.81,0) 5(1.27,0) 6(-1.27,0) 7(-3.81,0) 8(-6.35,0) 9(-8.89,0) 10(-11.43,0)
  silkscreen extent -13.08,-1.27 13.08,1.27, body extent -13,-1.27 13,1.27, height 8.59
DBV0005A_N [mm] "SOT23, 5-Leads, Body 2.9x1.6mm, Pitch 0.95mm, Lead Span 2.8mm, IPC Medium Density"
  rrect17% 1x0.6 smd: 1(-1.375,0.95) 2(-1.375,0) 3(-1.375,-0.95) 4(1.375,-0.95) 5(1.375,0.95)
  silkscreen extent -0.25,-1.55 0.25,1.55, body extent -1.42,-1.46 1.42,1.46, height 1.09
DBV0006A_N [mm] "SOT23, 6-Leads, Body 2.9x1.6mm, Pitch 0.95mm, Lead Span 2.8mm, IPC Medium Density"
  rrect17% 1x0.6 smd: 1(-1.375,0.95) 2(-1.375,0) 3(-1.375,-0.95) 4(1.375,-0.95) 5(1.375,0) 6(1.375,0.95)
  silkscreen extent -1.68,-1.55 0.5,1.55, body extent -1.42,-1.46 1.42,1.46, height 1.12
DCK0005A_N [mm] "SOT353, 5-Leads, Body 2x1.3mm, Pitch 0.65mm, Lead Span 2.1mm, IPC Medium Density"
  rrect25% 0.85x0.4 smd: 1(-1.125,0.65) 2(-1.125,0) 3(-1.125,-0.65) 4(1.125,-0.65) 5(1.125,0.65)
  silkscreen extent -1.48,-1.02 0.55,1.1, body extent -1.14,-1 1.14,1, height 0.95
DDC0006A_N [mm]
  rrect17% 1x0.6 smd: 1(-1.375,0.95) 2(-1.375,0) 3(-1.375,-0.95) 4(1.375,-0.95) 5(1.375,0) 6(1.375,0.95)
  silkscreen extent -1.75,-1.52 0.7,1.53, body extent -1.43,-1.48 1.43,1.49, height 0.92
DGK0008A_N [mm] "TSOP, 8-Leads, Body 3x3mm, Pitch 0.65mm, IPC Medium Density"
  oval 1.35x0.45 smd: 1(-2.225,0.975) 2(-2.225,0.325) 3(-2.225,-0.325) 4(-2.225,-0.975) 5(2.225,-0.975) 6(2.225,-0.325) 7(2.225,0.325) 8(2.225,0.975)
  silkscreen extent -2.75,-1.55 0.95,1.55, body extent -2.45,-1.5 2.45,1.5, height 0.96
DGN0008B_N [mm] "TSOP, 8-Leads, Body 3x3mm, Pitch 0.65mm, Thermal Pad 1.92x1.60mm, IPC Medium Density"
  rrect100% 1.35x0.45 smd: 1(-2.225,0.975) 2(-2.225,0.325) 3(-2.225,-0.325) 4(-2.225,-0.975) 5(2.225,-0.975) 6(2.225,-0.325) 7(2.225,0.325) 8(2.225,0.975)
  rrect5% 1.88x1.98 smd: 9(0,0)
  silkscreen extent -2.7,-1.55 0.95,1.55, body extent -2.46,-1.5 2.46,1.5, height 1.1
DGS0010A_N [mm] "TSSOP, 10-Leads, Body 3x3mm, Pitch 0.5mm, IPC Medium Density"
  oval 1.35x0.3 smd: 1(-2.225,1) 2(-2.225,0.5) 3(-2.225,0) 4(-2.225,-0.5) 5(-2.225,-1) 6(2.225,-1) 7(2.225,-0.5) 8(2.225,0) 9(2.225,0.5) 10(2.225,1)
  silkscreen extent -2.75,-1.55 0.9,1.55, body extent -2.45,-1.5 2.45,1.5, height 0.96
DSE0006A [mm] "TI recommended land pattern"
  rect 0.66x0.25 smd: 1(-0.62,0.5)
  rect 0.7x0.25 smd: 2(-0.6,0) 3(-0.6,-0.5) 4(0.6,-0.5) 5(0.6,0) 6(0.6,0.5)
  Top Layer region: -0.3,0.625 -0.25,0.625 -0.15,0.525 -0.15,0.375 -0.3,0.375
  silkscreen extent -0.9,-0.92 0.9,0.92, body extent -0.77,-0.77 0.77,0.77, height 0.8
FCC_disclaimer [mil]
Fiducial10-20 [mm]
  round 1 smd mask+0.5: 1(0,0)
  Top Layer keep-out circle w1.178: c0,0 r0.5
FP-885012206069_0603-MFG [mm]
  rrect13% 0.8x0.8 smd paste+0 mask+0: 1(-0.75,0) 2(0.75,0)
  body extent -1.25,-0.55 1.25,0.55, height 0.25
HCS_2512_122 [mm] "SMD, 2-Leads, Body 6.5x3.25mm"
  rect 1.8x3.4 smd: 1(-2.8,0) 2(2.8,0)
  silkscreen extent -1.5,-1.8 1.5,1.8, body extent -3.35,-1.62 3.35,1.63, height 1.22
Keystone5000 [mil] "For Keystone 500x miniature loop terminals"
  round 80 hole 40: 1(0,0)
  silkscreen extent -52,-52 52,52, body extent -49,-49 49,49, height 182
Keystone5001 [mil] "For Keystone 500x miniature loop terminals"
  round 80 hole 40: 1(0,0)
  silkscreen extent -52,-52 52,52, body extent -49,-49 49,49, height 182
Keystone5002 [mil] "For Keystone 500x miniature loop terminals"
  round 80 hole 40: 1(0,0)
  silkscreen extent -52,-52 52,52, body extent -49,-49 49,49, height 182
Keystone5003 [mil] "For Keystone 500x miniature loop terminals"
  round 80 hole 40: 1(0,0)
  silkscreen extent -52,-52 52,52, body extent -49,-49 49,49, height 182
Keystone5004 [mil] "For Keystone 500x miniature loop terminals"
  round 80 hole 40: 1(0,0)
  silkscreen extent -52,-52 52,52, body extent -49,-49 49,49, height 182
KTT0002A [mm] "TO-263-2"
  rrect10% 3.82x1.05 smd: 1(-6.9,2.54) 3(-6.9,-2.54)
  rrect1% 7.48x8.55 smd paste-4.2: 2(3.4,0)
  body extent -8.03,-5.08 7.05,5.08, height 4.67
MFP04A [mm] "FAIRCHILD optocoupler"
  rect 1.52x0.61 smd: 1(-3.175,0.635) 2(-3.175,-0.635) 3(3.175,-0.635) 4(3.175,0.635)
  silkscreen extent -2.28,-1.4 2.2,1.8, body extent -3.6,-1.34 3.6,1.34, height 2.39
Molex_1723161310 [mm] "Header(shrouded), 3.5mm, 5x2, R/A, TH"
  rrect50% 1.53x1.53 hole 1.02: 1(-7,5.455)
  round 1.53 hole 1.02: 2(-3.5,5.455) 3(0,5.455) 4(3.5,5.455) 5(7,5.455) 6(-7,2.455) 7(-3.5,2.455) 8(0,2.455) 9(3.5,2.455) 10(7,2.455)
  round 2.75 hole 3.05 unplated mask+0.102: ALIGN1(-5.25,-5.455) ALIGN2(5.25,-5.455)
  body extent -9.75,-12.9 9.75,5.77, height 13.56
N04C [mm] "FAIRCHILD"
  rect 1.3x1.5 smd mask+0.065: 1(-4.587,1.27) 2(-4.612,-1.27) 3(4.588,-1.27) 4(4.613,1.27)
  silkscreen extent -3.56,-2.3 3.56,2.72, body extent -5.08,-2.3 5.08,2.3, height 3.87
PG-TSDSON-8 [mm] "Infineon recommended land pattern"
  rect 0.8x0.34 smd: 1(-1.538,0.975) 2(-1.538,0.325) 3(-1.538,-0.325) 4(-1.538,-0.975)
  rect 0.65x0.34 smd: 5(1.538,-0.975) 6(1.538,-0.325) 7(1.538,0.325) 8(1.538,0.975)
  rect 1.71x2.29 smd: 9(0.358,0)
  silkscreen extent -2.22,-1.8 2.22,1.8, body extent -1.7,-1.7 1.7,1.7, height 1.1
Pulse_J0B-3563NL [mm] "12 Port RJ45, R/A, TH"
  rrect50% 1.37x1.37 hole 0.914: A1(9.27,38.61) B1(9.27,32) C1(9.27,24.64) D1(9.27,18.03) E1(9.27,10.67) F1(9.27,4.06) G1(9.27,-3.3) H1(9.27,-9.91) I1(9.27,-17.27) J1(9.27,-23.88) K1(9.27,-31.24) L1(9.27,-37.85)
  round 1.37 hole 0.914: A2(10.54,37.34) A3(11.81,38.61) A4(13.08,37.34) A5(14.35,38.61) A6(15.62,37.34) A7(16.89,38.61) A8(18.16,37.34) A9(19.43,38.61) A10(20.7,37.34) A11(24.51,38.61) A12(25.78,37.34) A13(27.05,38.61) A14(28.32,37.34) B2(10.54,33.27) B3(11.81,32) B4(13.08,33.27) B5(14.35,32) B6(15.62,33.27) B7(16.89,32) B8(18.16,33.27) B9(19.43,32) B10(20.7,33.27) B11(24.51,32) B12(25.78,33.27) B13(27.05,32) B14(28.32,33.27) C2(10.54,23.37) C3(11.81,24.64) C4(13.08,23.37) C5(14.35,24.64) C6(15.62,23.37) C7(16.89,24.64) C8(18.16,23.37) C9(19.43,24.64) C10(20.7,23.37) C11(24.51,24.64) C12(25.78,23.37) C13(27.05,24.64) C14(28.32,23.37) D2(10.54,19.3) D3(11.81,18.03) D4(13.08,19.3) D5(14.35,18.03) D6(15.62,19.3) D7(16.89,18.03) D8(18.16,19.3) D9(19.43,18.03) D10(20.7,19.3) D11(24.51,18.03) D12(25.78,19.3) D13(27.05,18.03) D14(28.32,19.3) E2(10.54,9.4) E3(11.81,10.67) E4(13.08,9.4) E5(14.35,10.67) E6(15.62,9.4) E7(16.89,10.67) E8(18.16,9.4) E9(19.43,10.67) E10(20.7,9.4) E11(24.51,10.67) E12(25.78,9.4) E13(27.05,10.67) E14(28.32,9.4) F2(10.54,5.33) F3(11.81,4.06) F4(13.08,5.33) F5(14.35,4.06) F6(15.62,5.33) F7(16.89,4.06) F8(18.16,5.33) F9(19.43,4.06) F10(20.7,5.33) F11(24.51,4.06) F12(25.78,5.33) F13(27.05,4.06) F14(28.32,5.33) G2(10.54,-4.57) G3(11.81,-3.3) G4(13.08,-4.57) G5(14.35,-3.3) G6(15.62,-4.57) G7(16.89,-3.3) G8(18.16,-4.57) G9(19.43,-3.3) G10(20.7,-4.57) G11(24.51,-3.3) G12(25.78,-4.57) G13(27.05,-3.3) G14(28.32,-4.57) H2(10.54,-8.64) H3(11.81,-9.91) H4(13.08,-8.64) H5(14.35,-9.91) H6(15.62,-8.64) H7(16.89,-9.91) H8(18.16,-8.64) H9(19.43,-9.91) H10(20.7,-8.64) H11(24.51,-9.91) H12(25.78,-8.64) H13(27.05,-9.91) H14(28.32,-8.64) I2(10.54,-18.54) I3(11.81,-17.27) I4(13.08,-18.54) I5(14.35,-17.27) I6(15.62,-18.54) I7(16.89,-17.27) I8(18.16,-18.54) I9(19.43,-17.27) I10(20.7,-18.54) I11(24.51,-17.27) I12(25.78,-18.54) I13(27.05,-17.27) I14(28.32,-18.54) J2(10.54,-22.61) J3(11.81,-23.88) J4(13.08,-22.61) J5(14.35,-23.88) J6(15.62,-22.61) J7(16.89,-23.88) J8(18.16,-22.61) J9(19.43,-23.88) J10(20.7,-22.61) J11(24.51,-23.88) J12(25.78,-22.61) J13(27.05,-23.88) J14(28.32,-22.61) K2(10.54,-32.51) K3(11.81,-31.24) K4(13.08,-32.51) K5(14.35,-31.24) K6(15.62,-32.51) K7(16.89,-31.24) K8(18.16,-32.51) K9(19.43,-31.24) K10(20.7,-32.51) K11(24.51,-31.24) K12(25.78,-32.51) K13(27.05,-31.24) K14(28.32,-32.51) L2(10.54,-36.58) L3(11.81,-37.85) L4(13.08,-36.58) L5(14.35,-37.85) L6(15.62,-36.58) L7(16.89,-37.85) L8(18.16,-36.58) L9(19.43,-37.85) L10(20.7,-36.58) L11(24.51,-37.85) L12(25.78,-36.58) L13(27.05,-37.85) L14(28.32,-36.58)
  round 1.524 hole 1.016: A15(1.52,41.47) A16(1.52,38.93) A18(2.28,28.39) C16(2.28,24.96) C18(2.28,14.42) E16(2.28,10.99) E18(2.28,0.45) G16(2.28,-2.98) G18(2.28,-13.52) I16(2.28,-16.95) I18(2.28,-27.49) K16(2.28,-30.92) K17(1.52,-38.93) K18(1.52,-41.47)
  round 1.3 hole 1.016: A17(0.76,30.93) C15(0.76,27.5) C17(0.76,16.96) E15(0.76,13.53) E17(0.76,2.99) G15(0.76,-0.44) G17(0.76,-10.98) I15(0.76,-14.41) I17(0.76,-24.95) K15(0.76,-28.38)
  round 1.715 hole 1.143: B15(33.27,41.02) B16(33.27,38.48) B17(33.27,31.37) D16(33.27,24.51) D17(33.27,17.4) F16(33.27,10.54) F17(33.27,3.43) H16(33.27,-3.43) H17(33.27,-10.54) J16(33.27,-17.4) J17(33.27,-24.51) L16(33.27,-31.37) L17(33.27,-38.48) L18(33.27,-41.02)
  round 1.65 hole 1.143: B18(33.27,28.83) D15(33.27,27.05) D18(33.27,14.86) F15(33.27,13.08) F18(33.27,0.89) H15(33.27,-0.89) H18(33.27,-13.08) J15(33.27,-14.86) J18(33.27,-27.05) L15(33.27,-28.83)
  round 2.95 hole 3.25 unplated mask+0.102: MH1(4.57,40.64) MH2(4.57,-40.64)
  round 2.355 hole 1.57: S1(0,43.435) S2(20.06,43.435) S3(30.35,43.435) S4(0,-43.435) S5(16,-43.435) S6(30.35,-43.435)
  body extent -6.91,-44.88 34.96,44.89, height 26.85
PW0008A_L [mm] "TSOP, 8-Leads, Body 3x4.4mm, Pitch 0.65mm, IPC High Density"
  oval 1.2x0.4 smd: 1(-2.85,0.975) 2(-2.85,0.325) 3(-2.85,-0.325) 4(-2.85,-0.975) 5(2.85,-0.975) 6(2.85,-0.325) 7(2.85,0.325) 8(2.85,0.975)
  silkscreen extent -3.2,-1.55 1.85,1.55, body extent -3.21,-1.5 3.21,1.5, height 1.2
Samtec_SSW-108-01-x-D [mm] "Receptacle, 2.54mm, 8x2, TH"
  rect 1.55x1.55 hole 1.04: 1(-8.89,1.27)
  round 1.55 hole 1.04: 2(-8.89,-1.27) 3(-6.35,1.27) 4(-6.35,-1.27) 5(-3.81,1.27) 6(-3.81,-1.27) 7(-1.27,1.27) 8(-1.27,-1.27) 9(1.27,1.27) 10(1.27,-1.27) 11(3.81,1.27) 12(3.81,-1.27) 13(6.35,1.27) 14(6.35,-1.27) 15(8.89,1.27) 16(8.89,-1.27)
  silkscreen extent -10.41,-2.48 10.41,3, body extent -10.41,-2.48 10.41,2.48, height 8.51
Samtec_SSW-112-01-x-D [mm] "Receptacle, 12x2, 2.54mm, TH"
  rect 1.55x1.55 hole 1.04: 1(-13.97,1.27)
  round 1.55 hole 1.04: 2(-13.97,-1.27) 3(-11.43,1.27) 4(-11.43,-1.27) 5(-8.89,1.27) 6(-8.89,-1.27) 7(-6.35,1.27) 8(-6.35,-1.27) 9(-3.81,1.27) 10(-3.81,-1.27) 11(-1.27,1.27) 12(-1.27,-1.27) 13(1.27,1.27) 14(1.27,-1.27) 15(3.81,1.27) 16(3.81,-1.27) 17(6.35,1.27) 18(6.35,-1.27) 19(8.89,1.27) 20(8.89,-1.27) 21(11.43,1.27) 22(11.43,-1.27) 23(13.97,1.27) 24(13.97,-1.27)
  silkscreen extent -15.9,-2.48 15.49,2.48, body extent -15.49,-2.48 15.49,2.48, height 8.51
